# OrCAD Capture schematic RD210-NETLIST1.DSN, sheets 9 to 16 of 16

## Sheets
9 8: size Custom
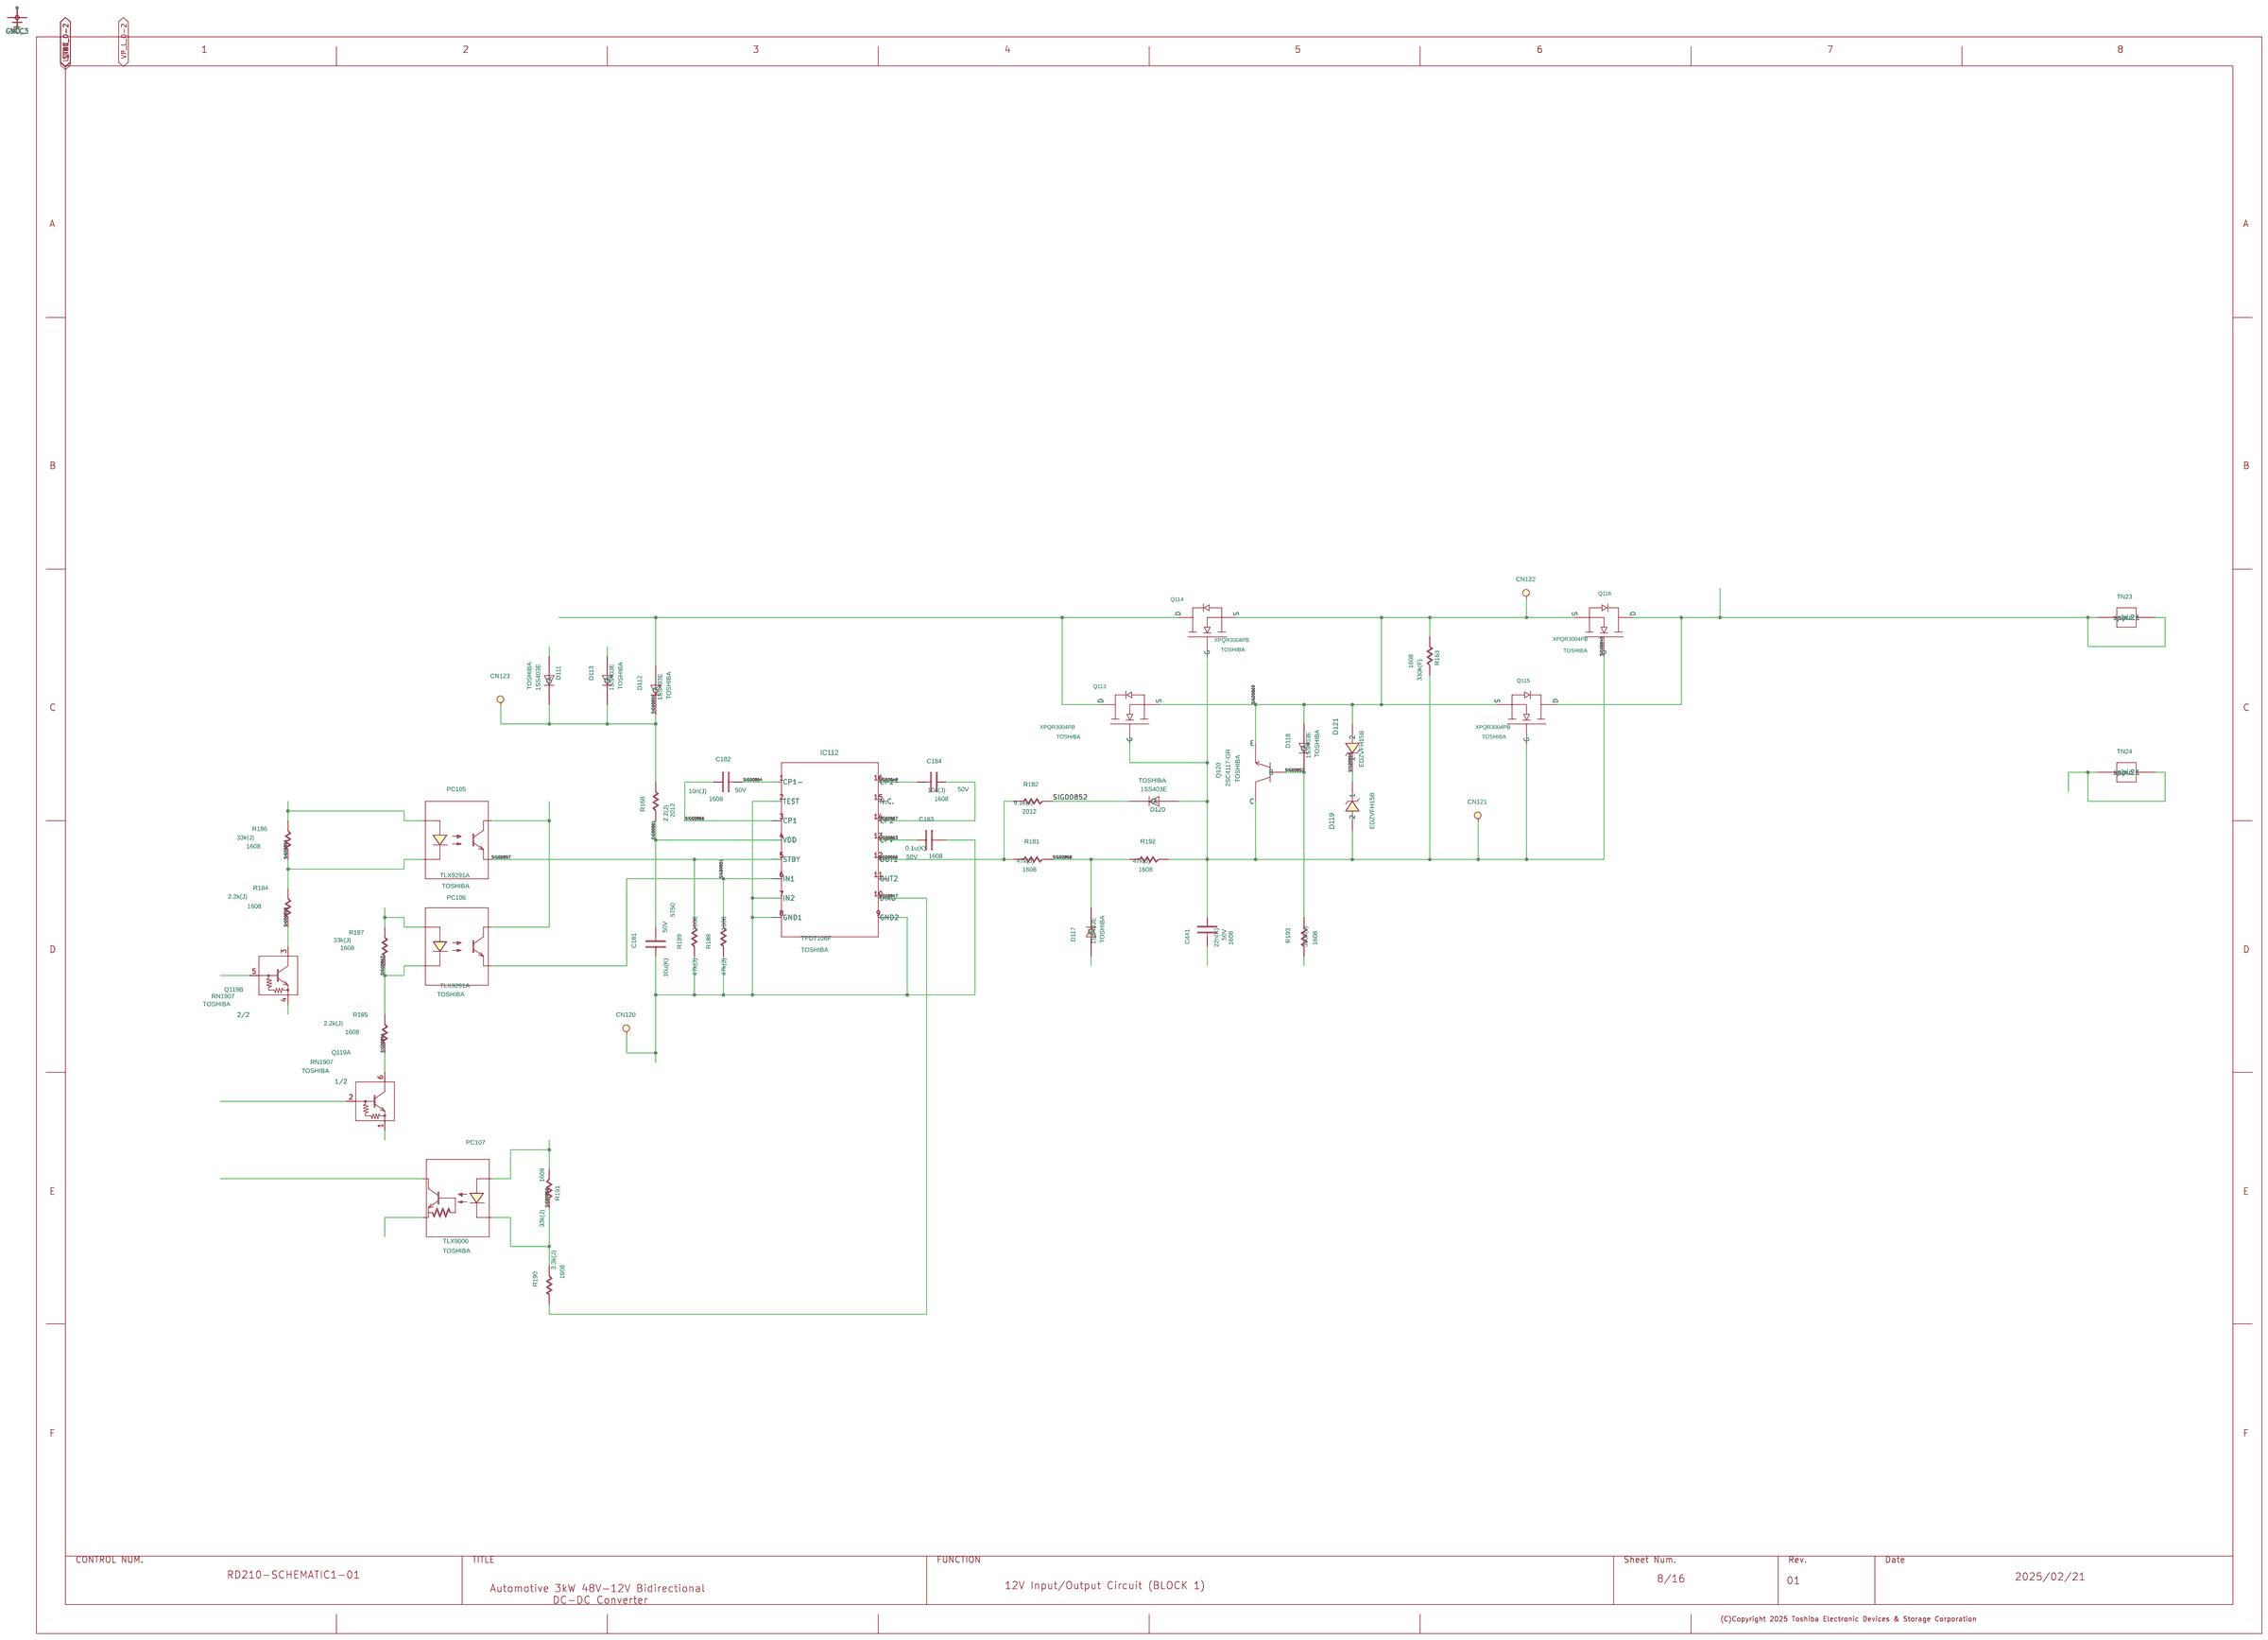
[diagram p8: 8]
10 7: size Custom
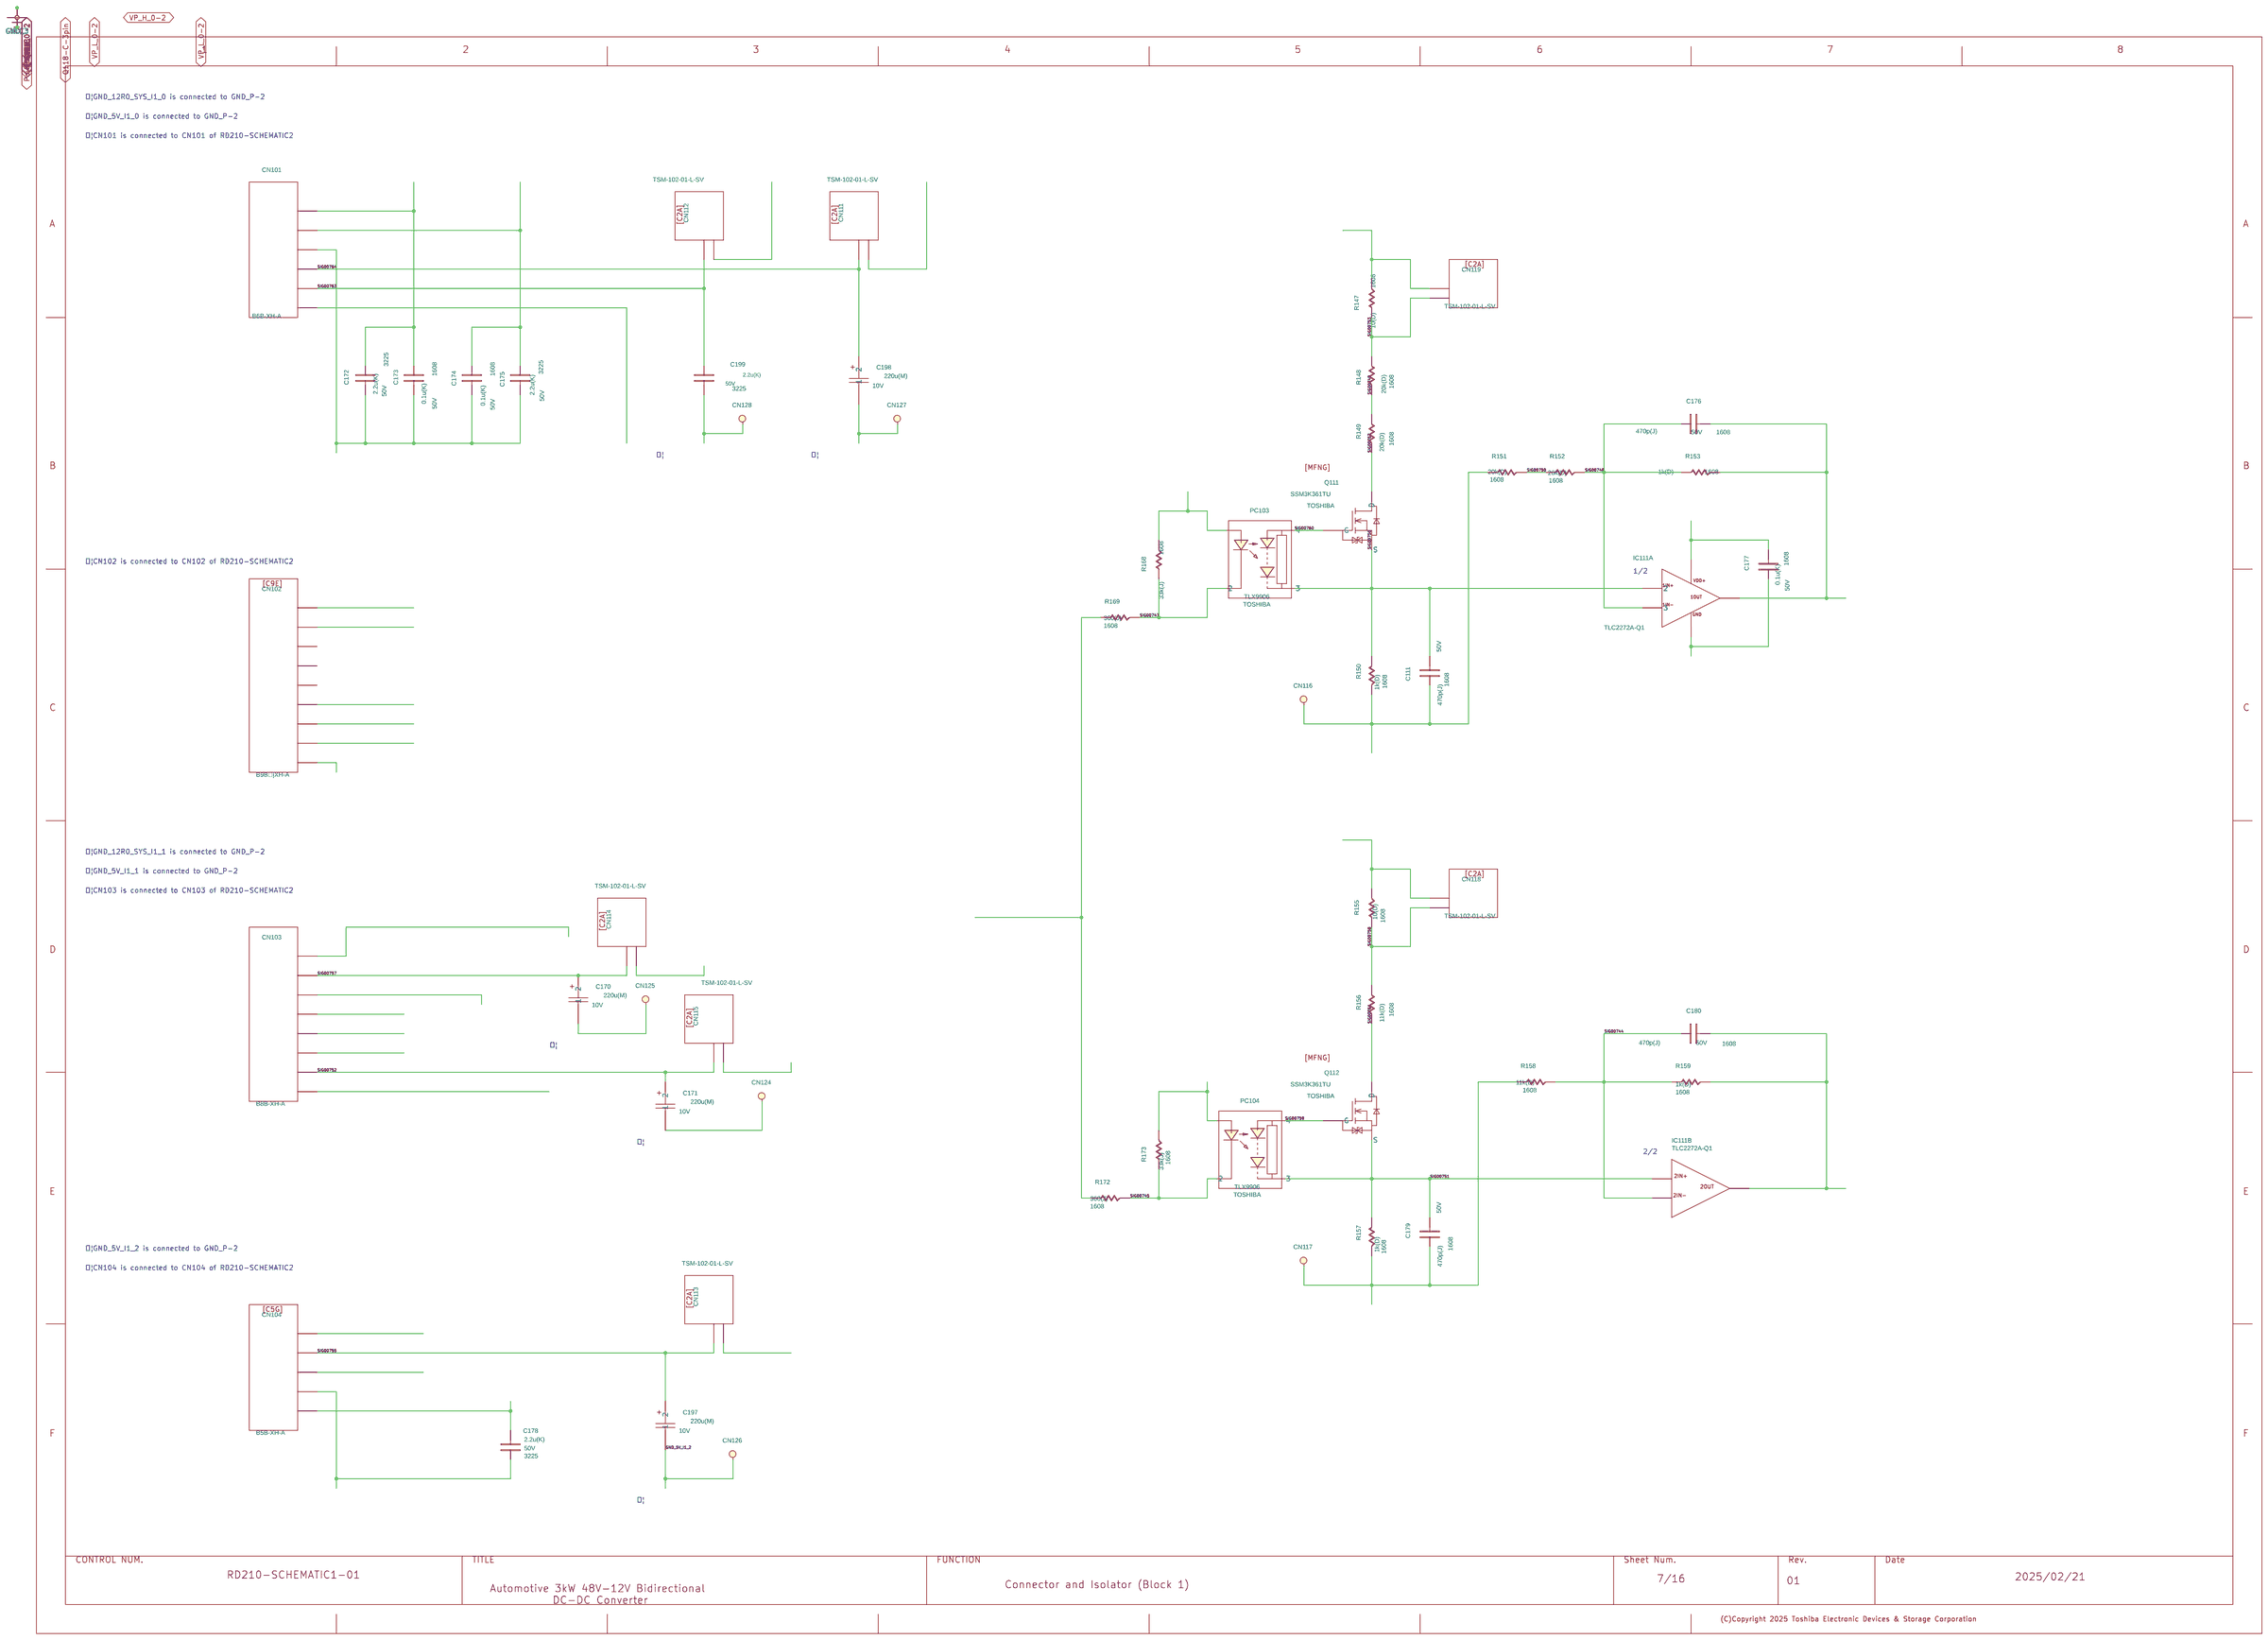
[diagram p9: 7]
11 6: size Custom
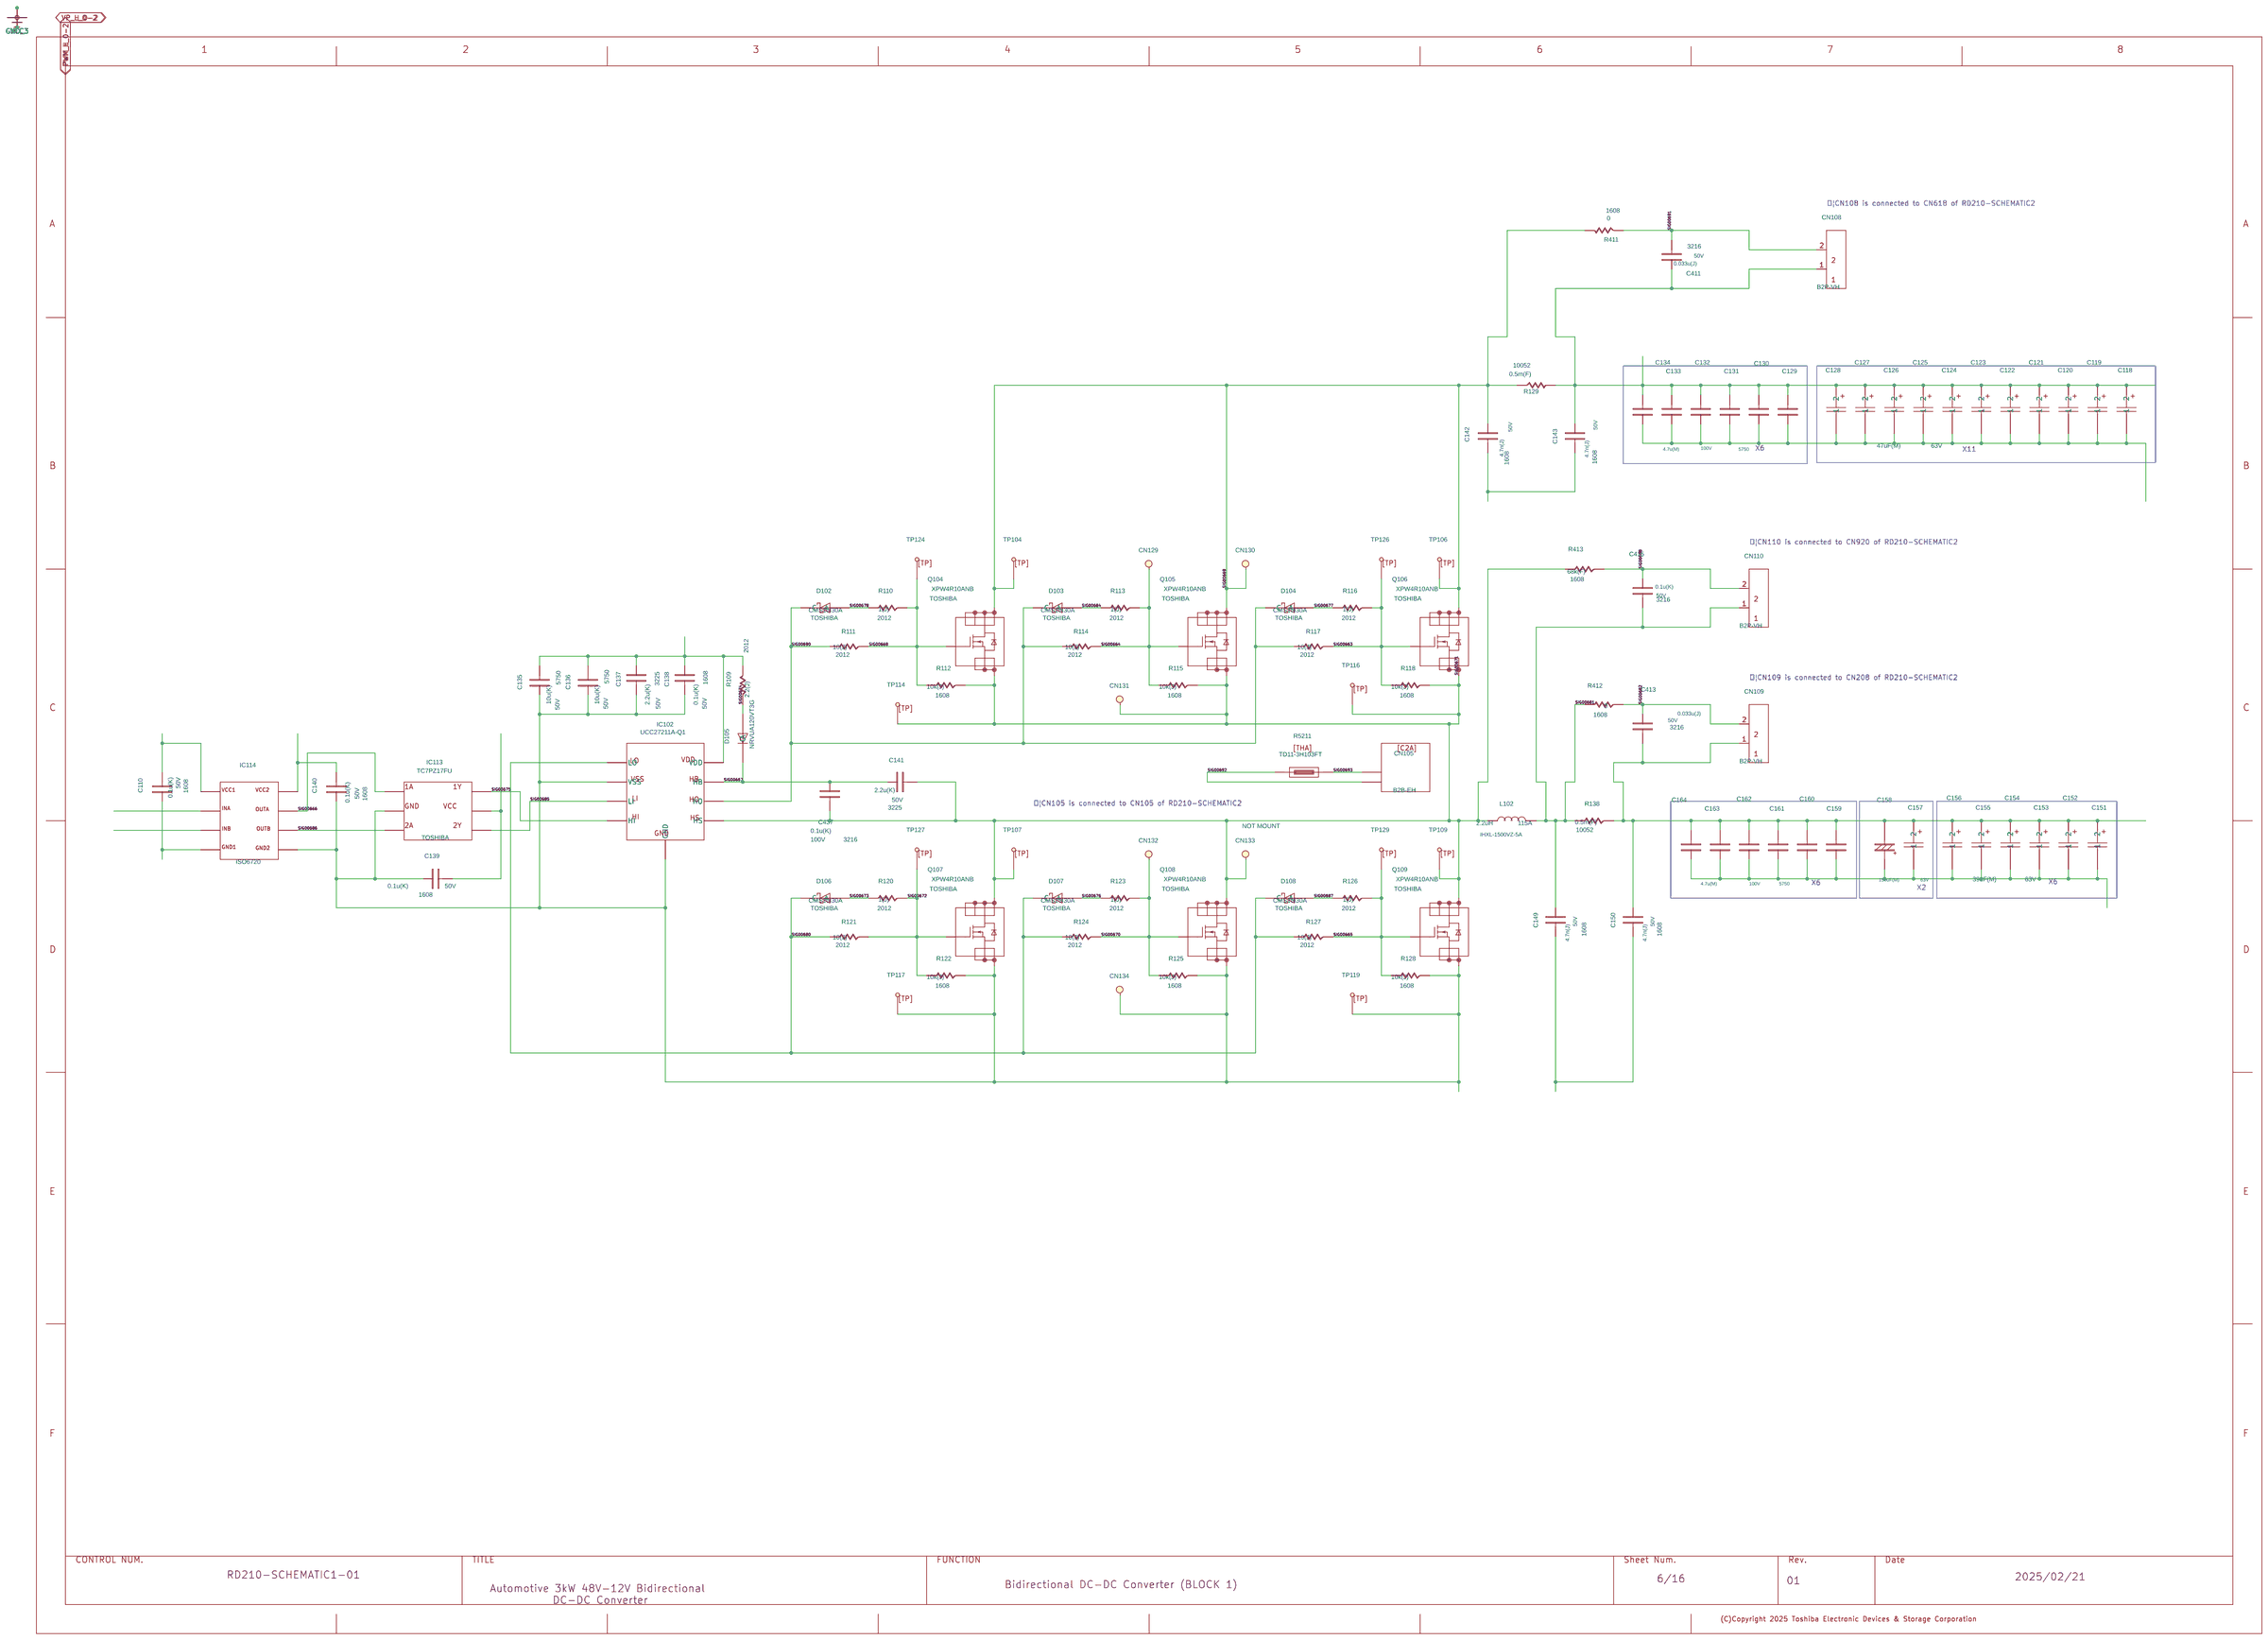
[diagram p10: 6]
12 5: size Custom
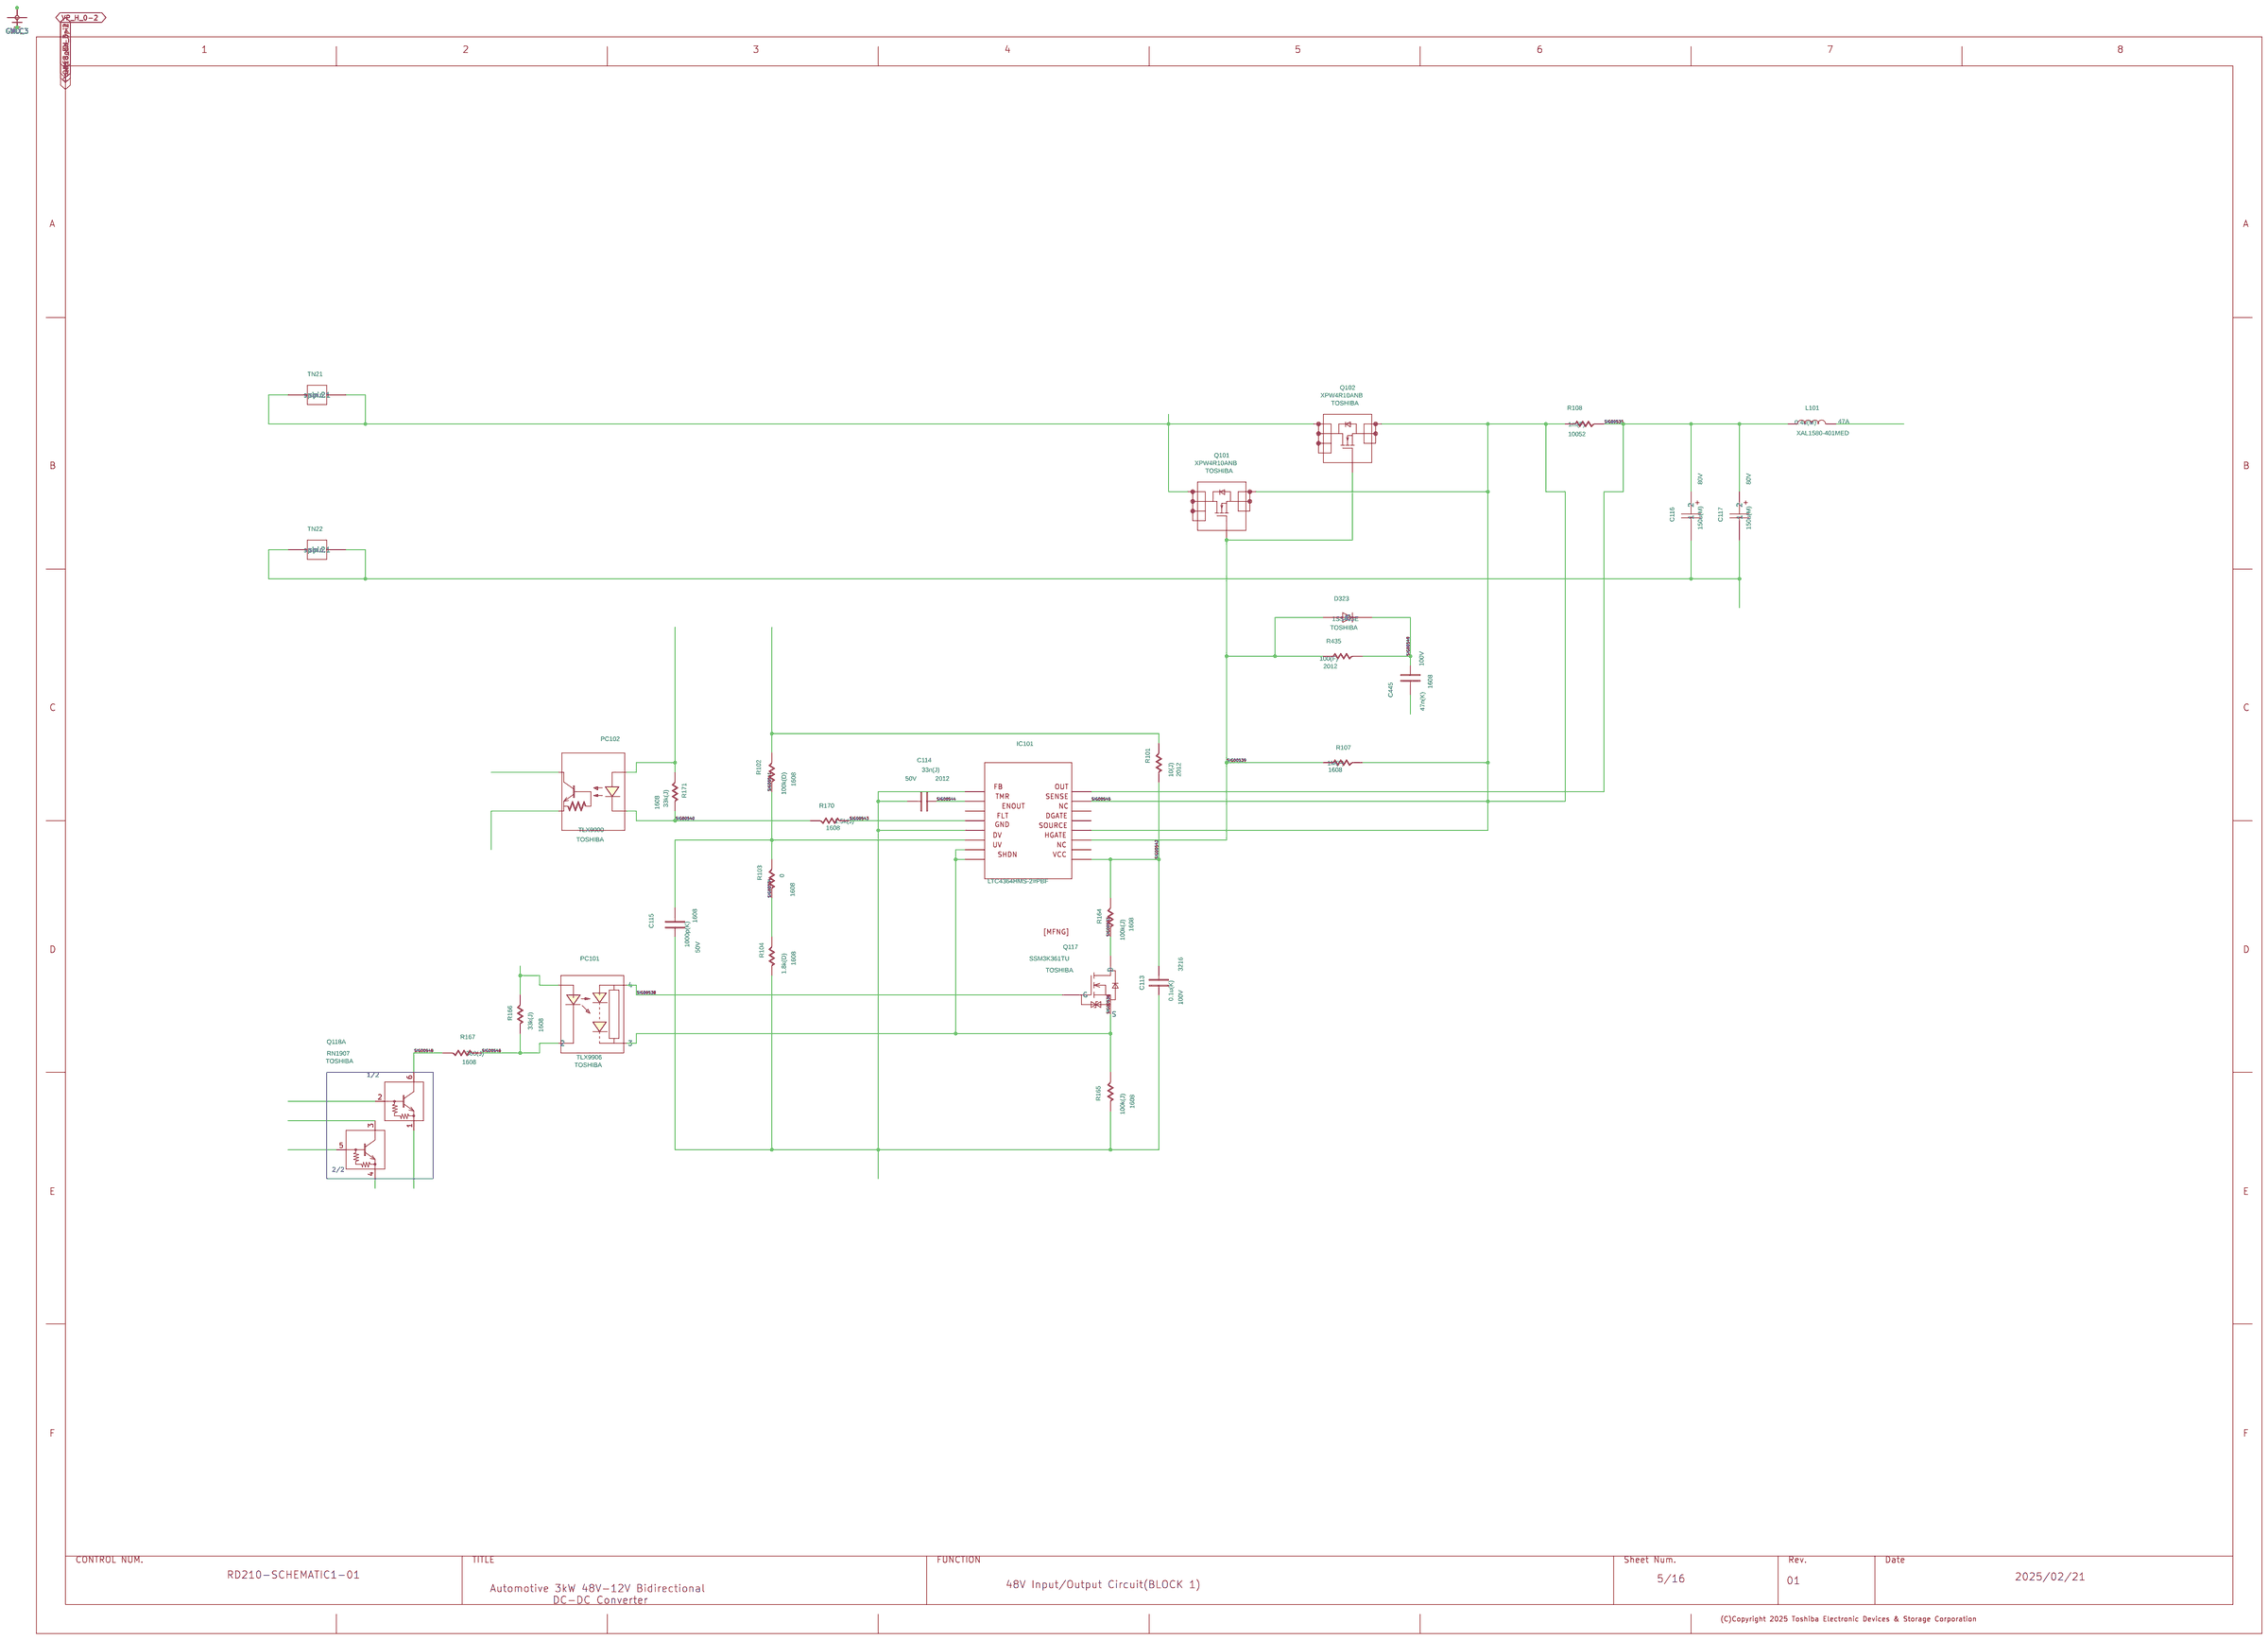
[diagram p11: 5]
13 4: size Custom
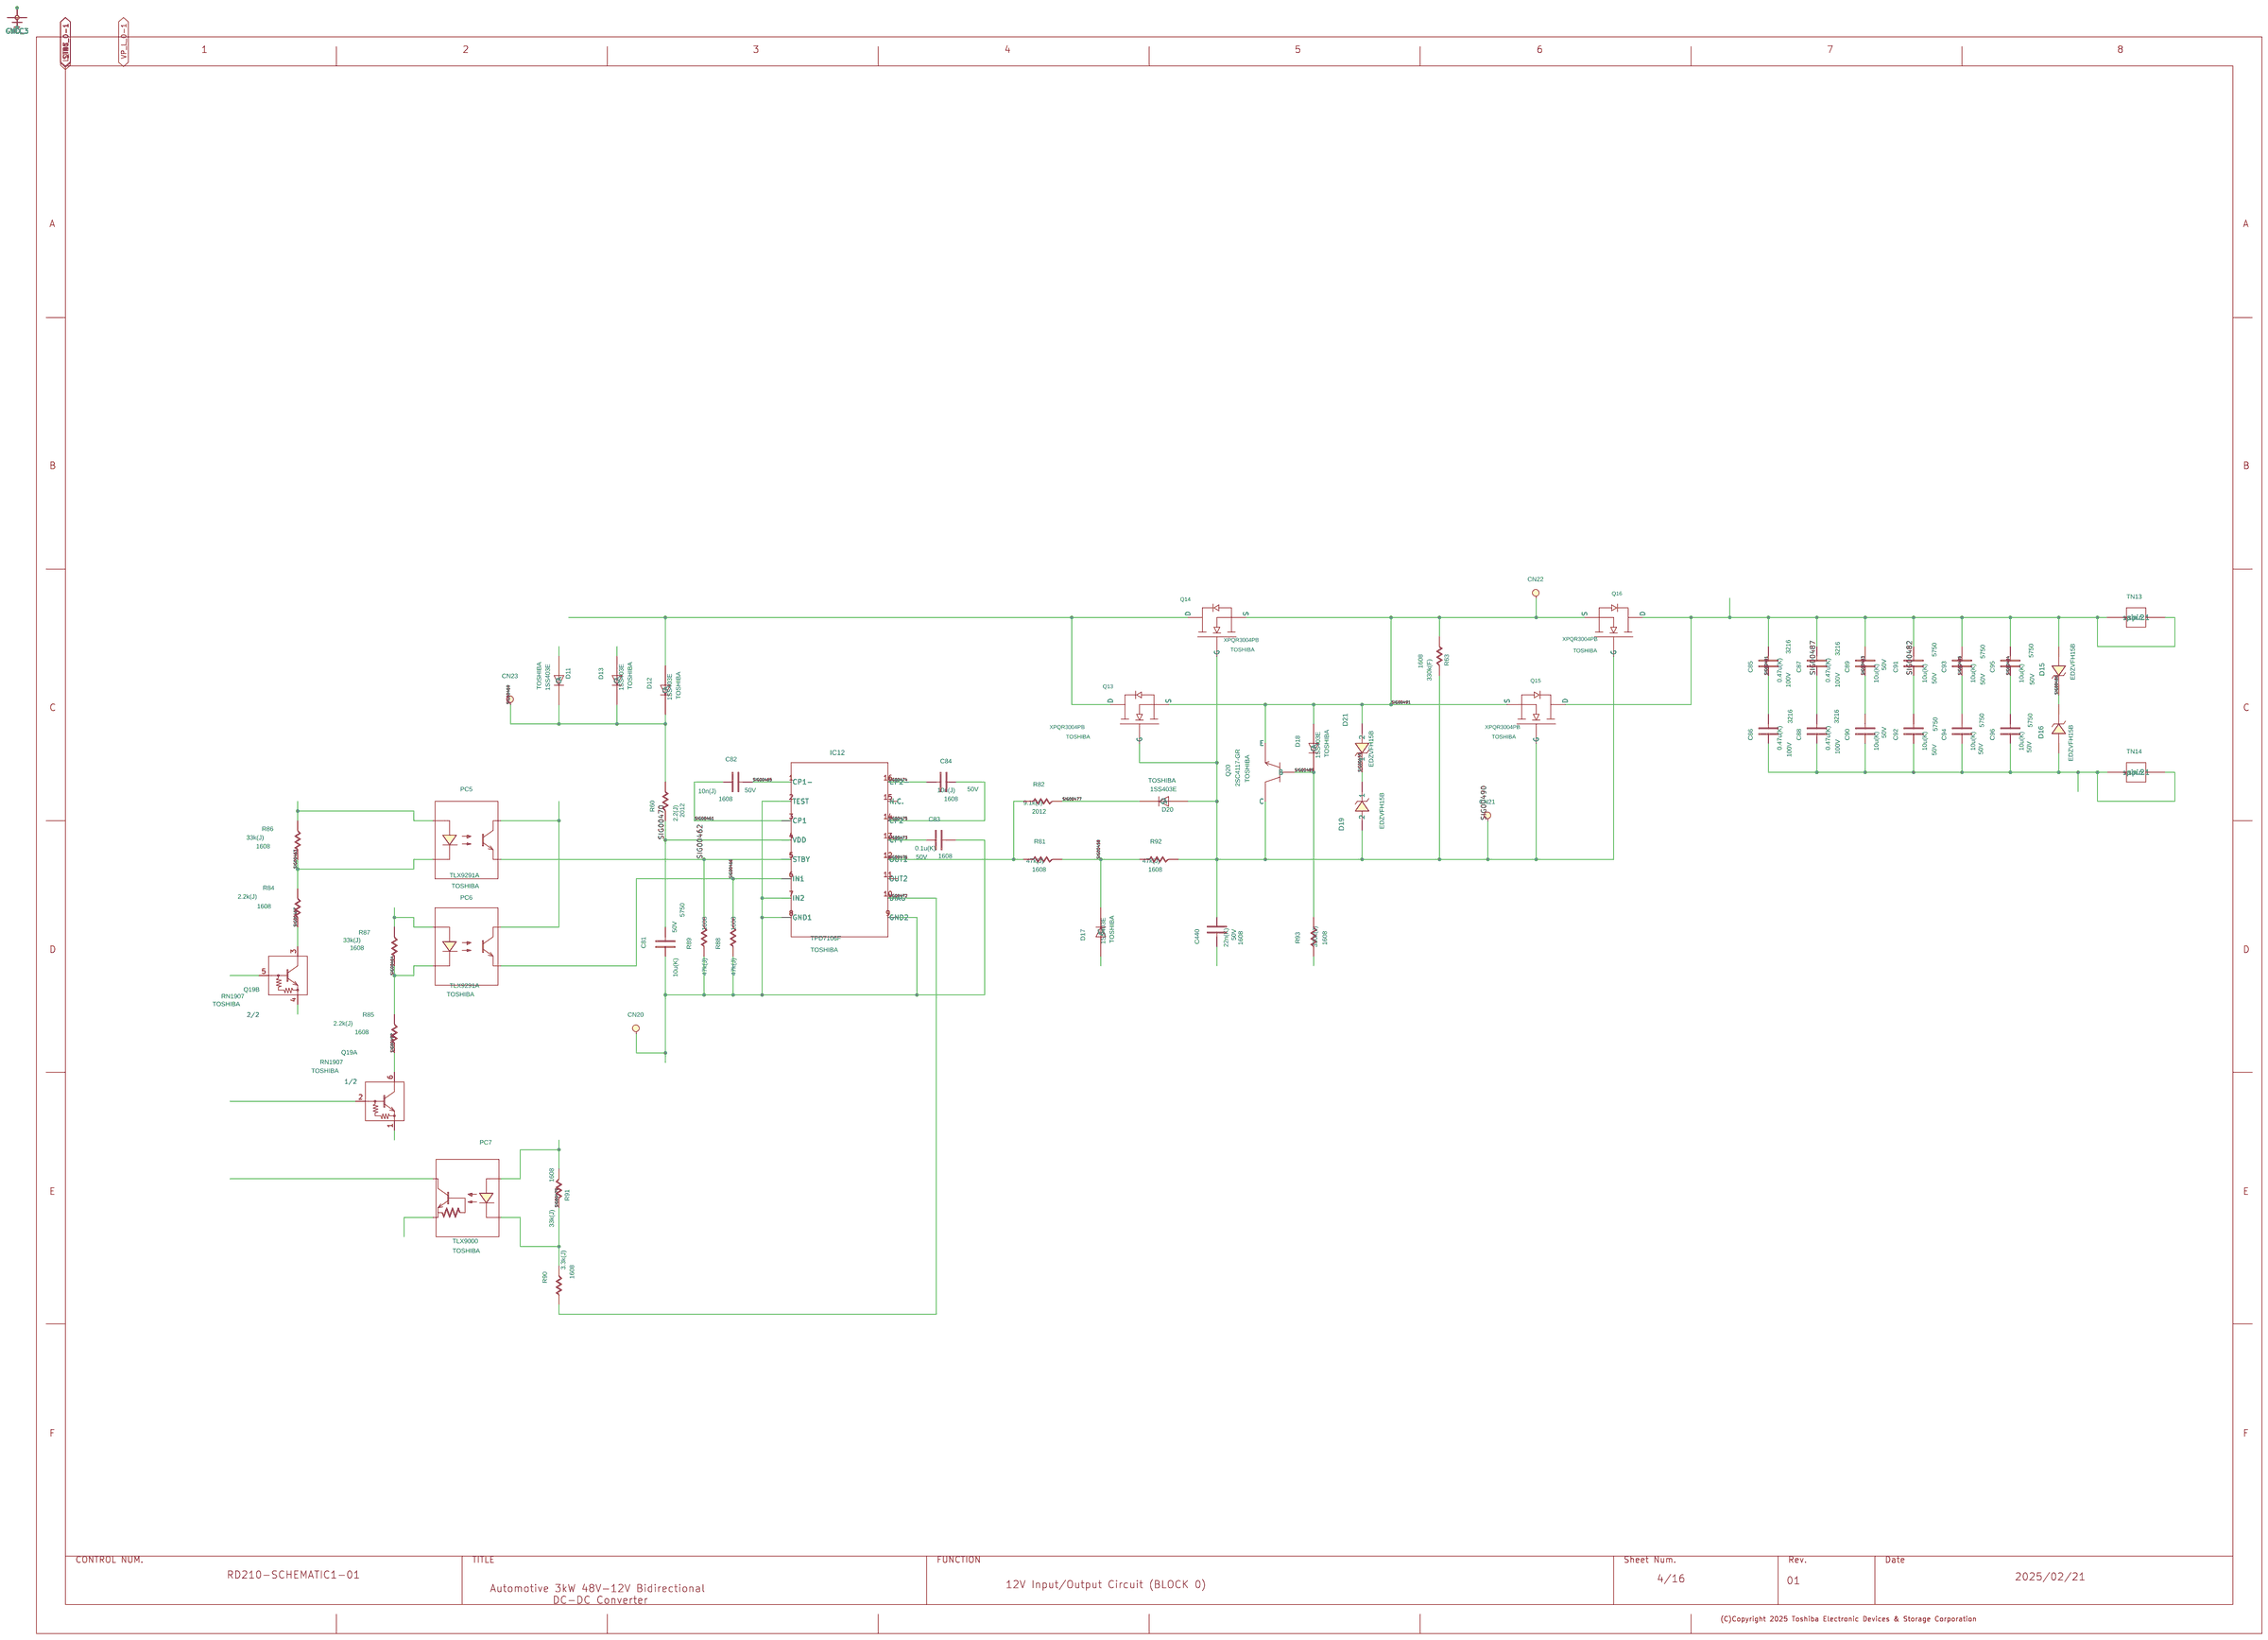
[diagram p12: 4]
14 3: size Custom
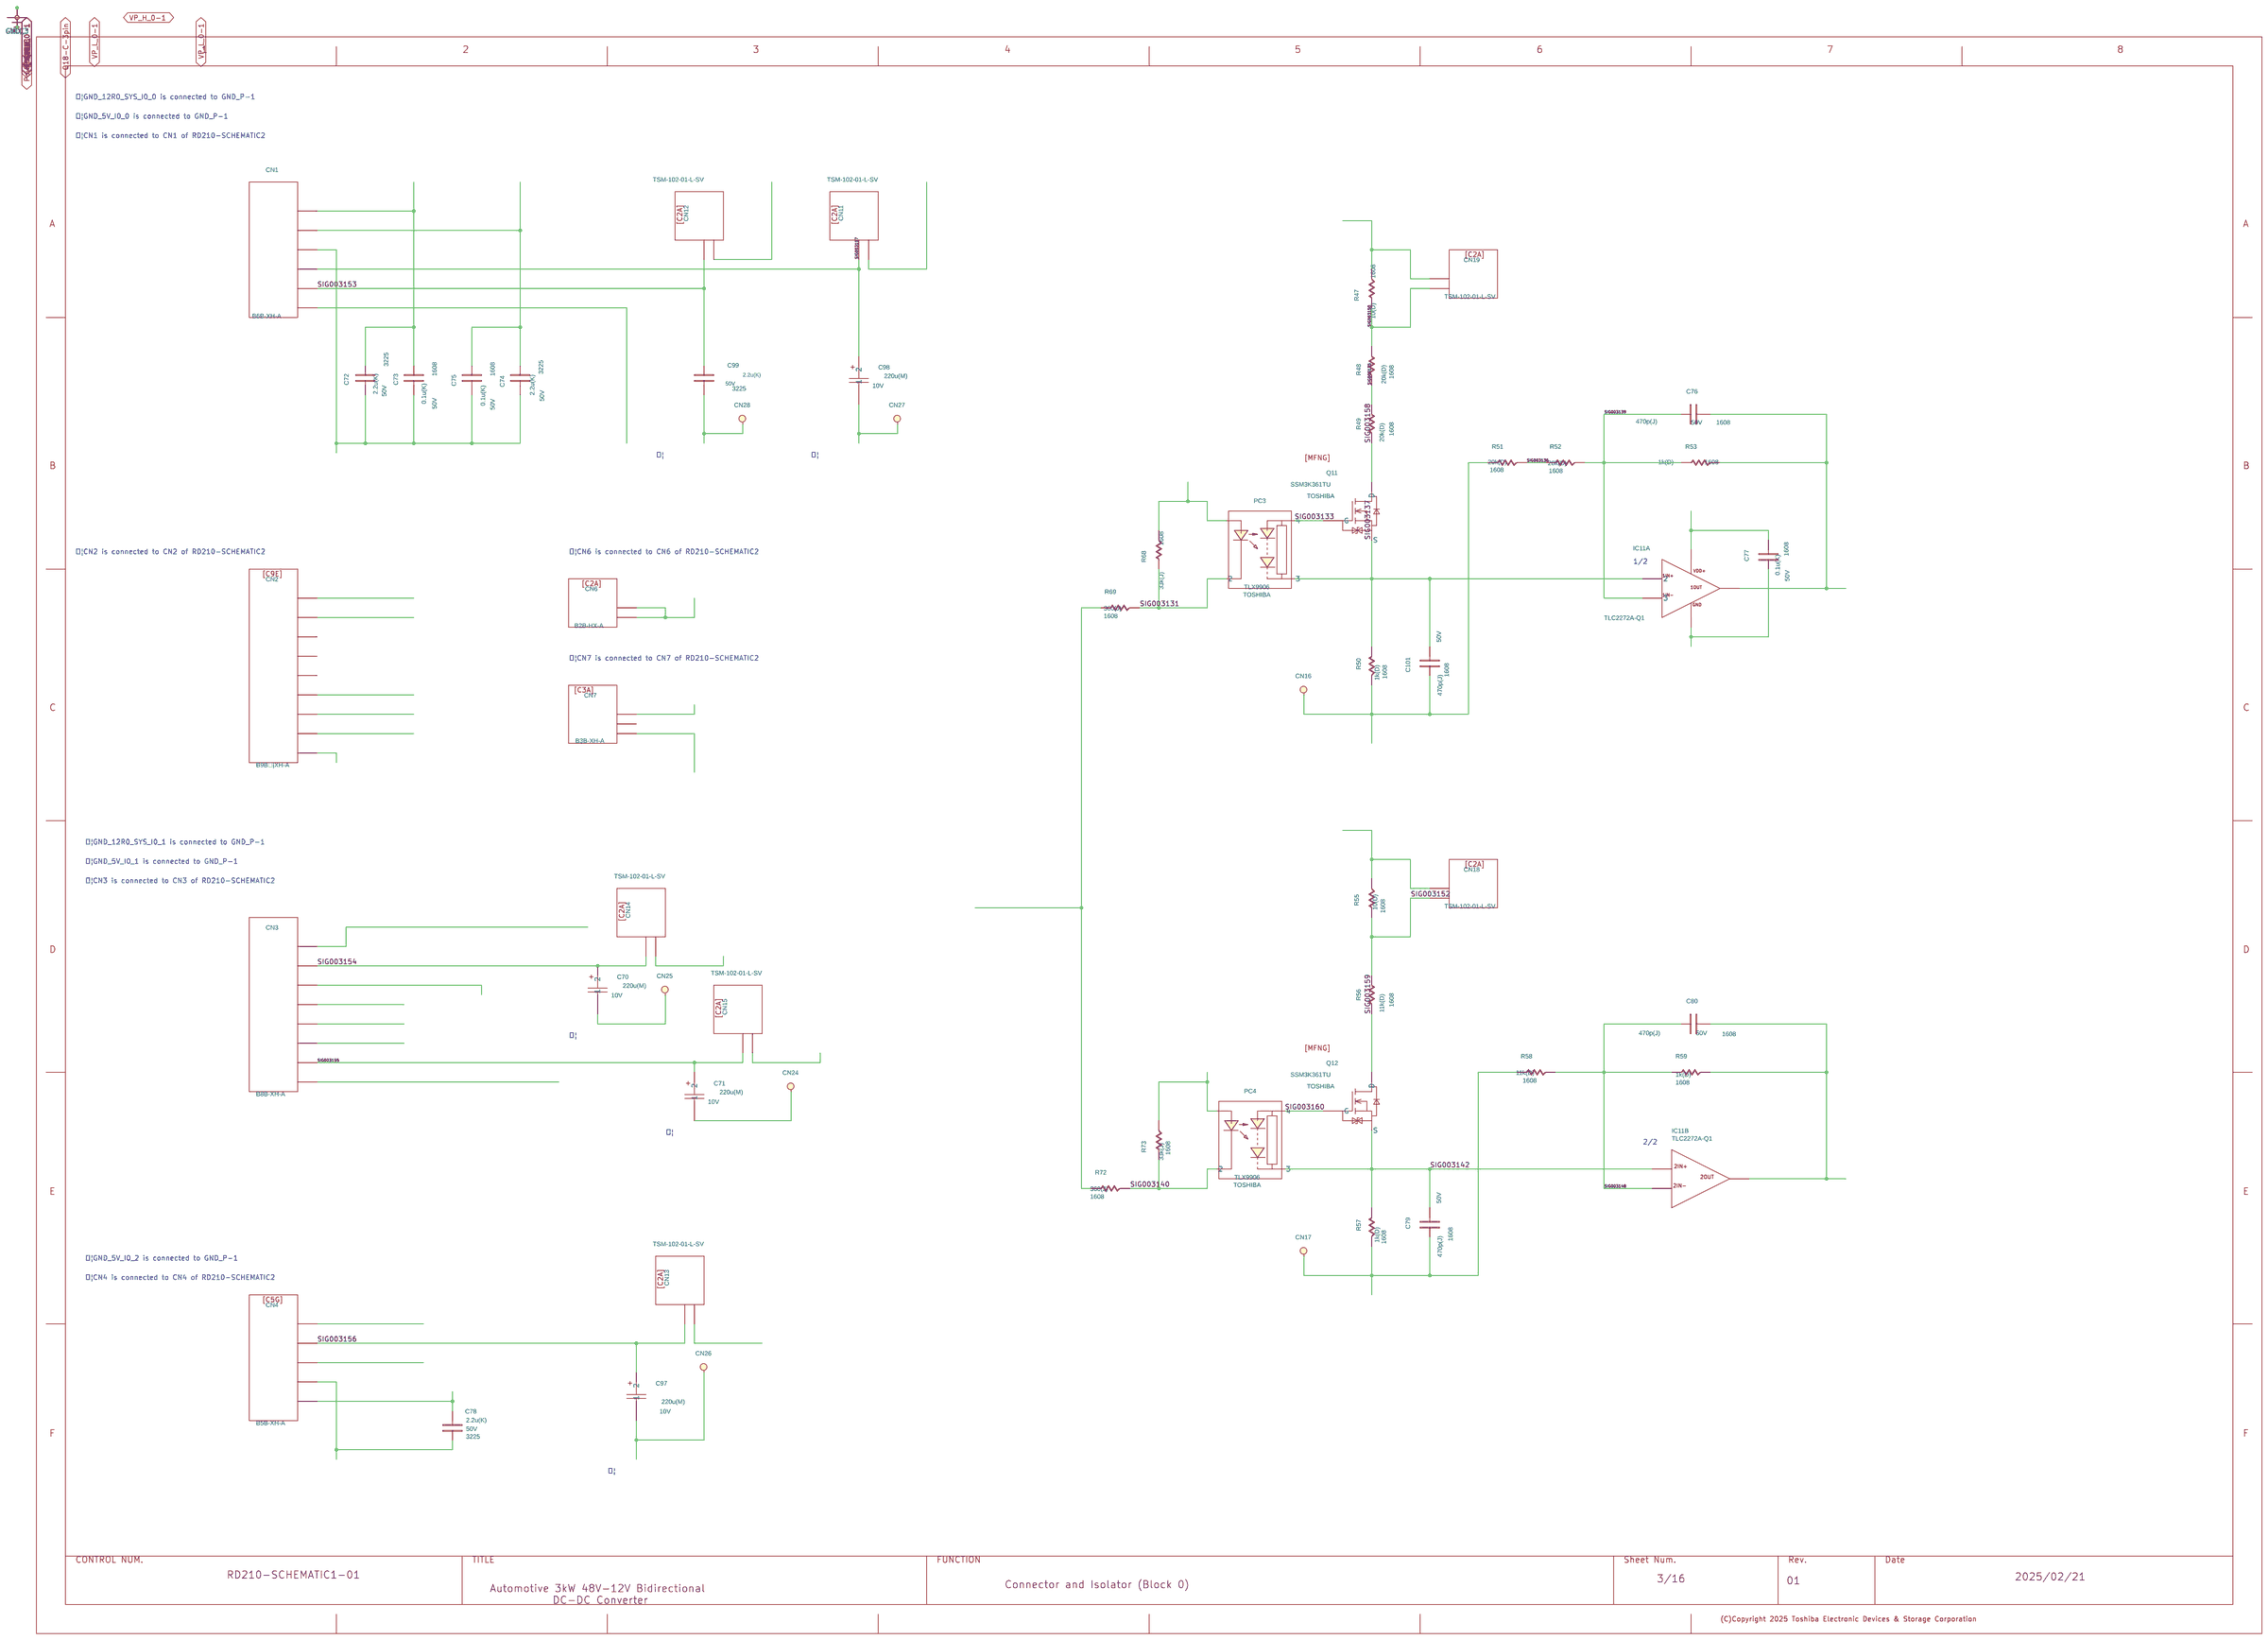
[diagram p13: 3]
15 2: size Custom
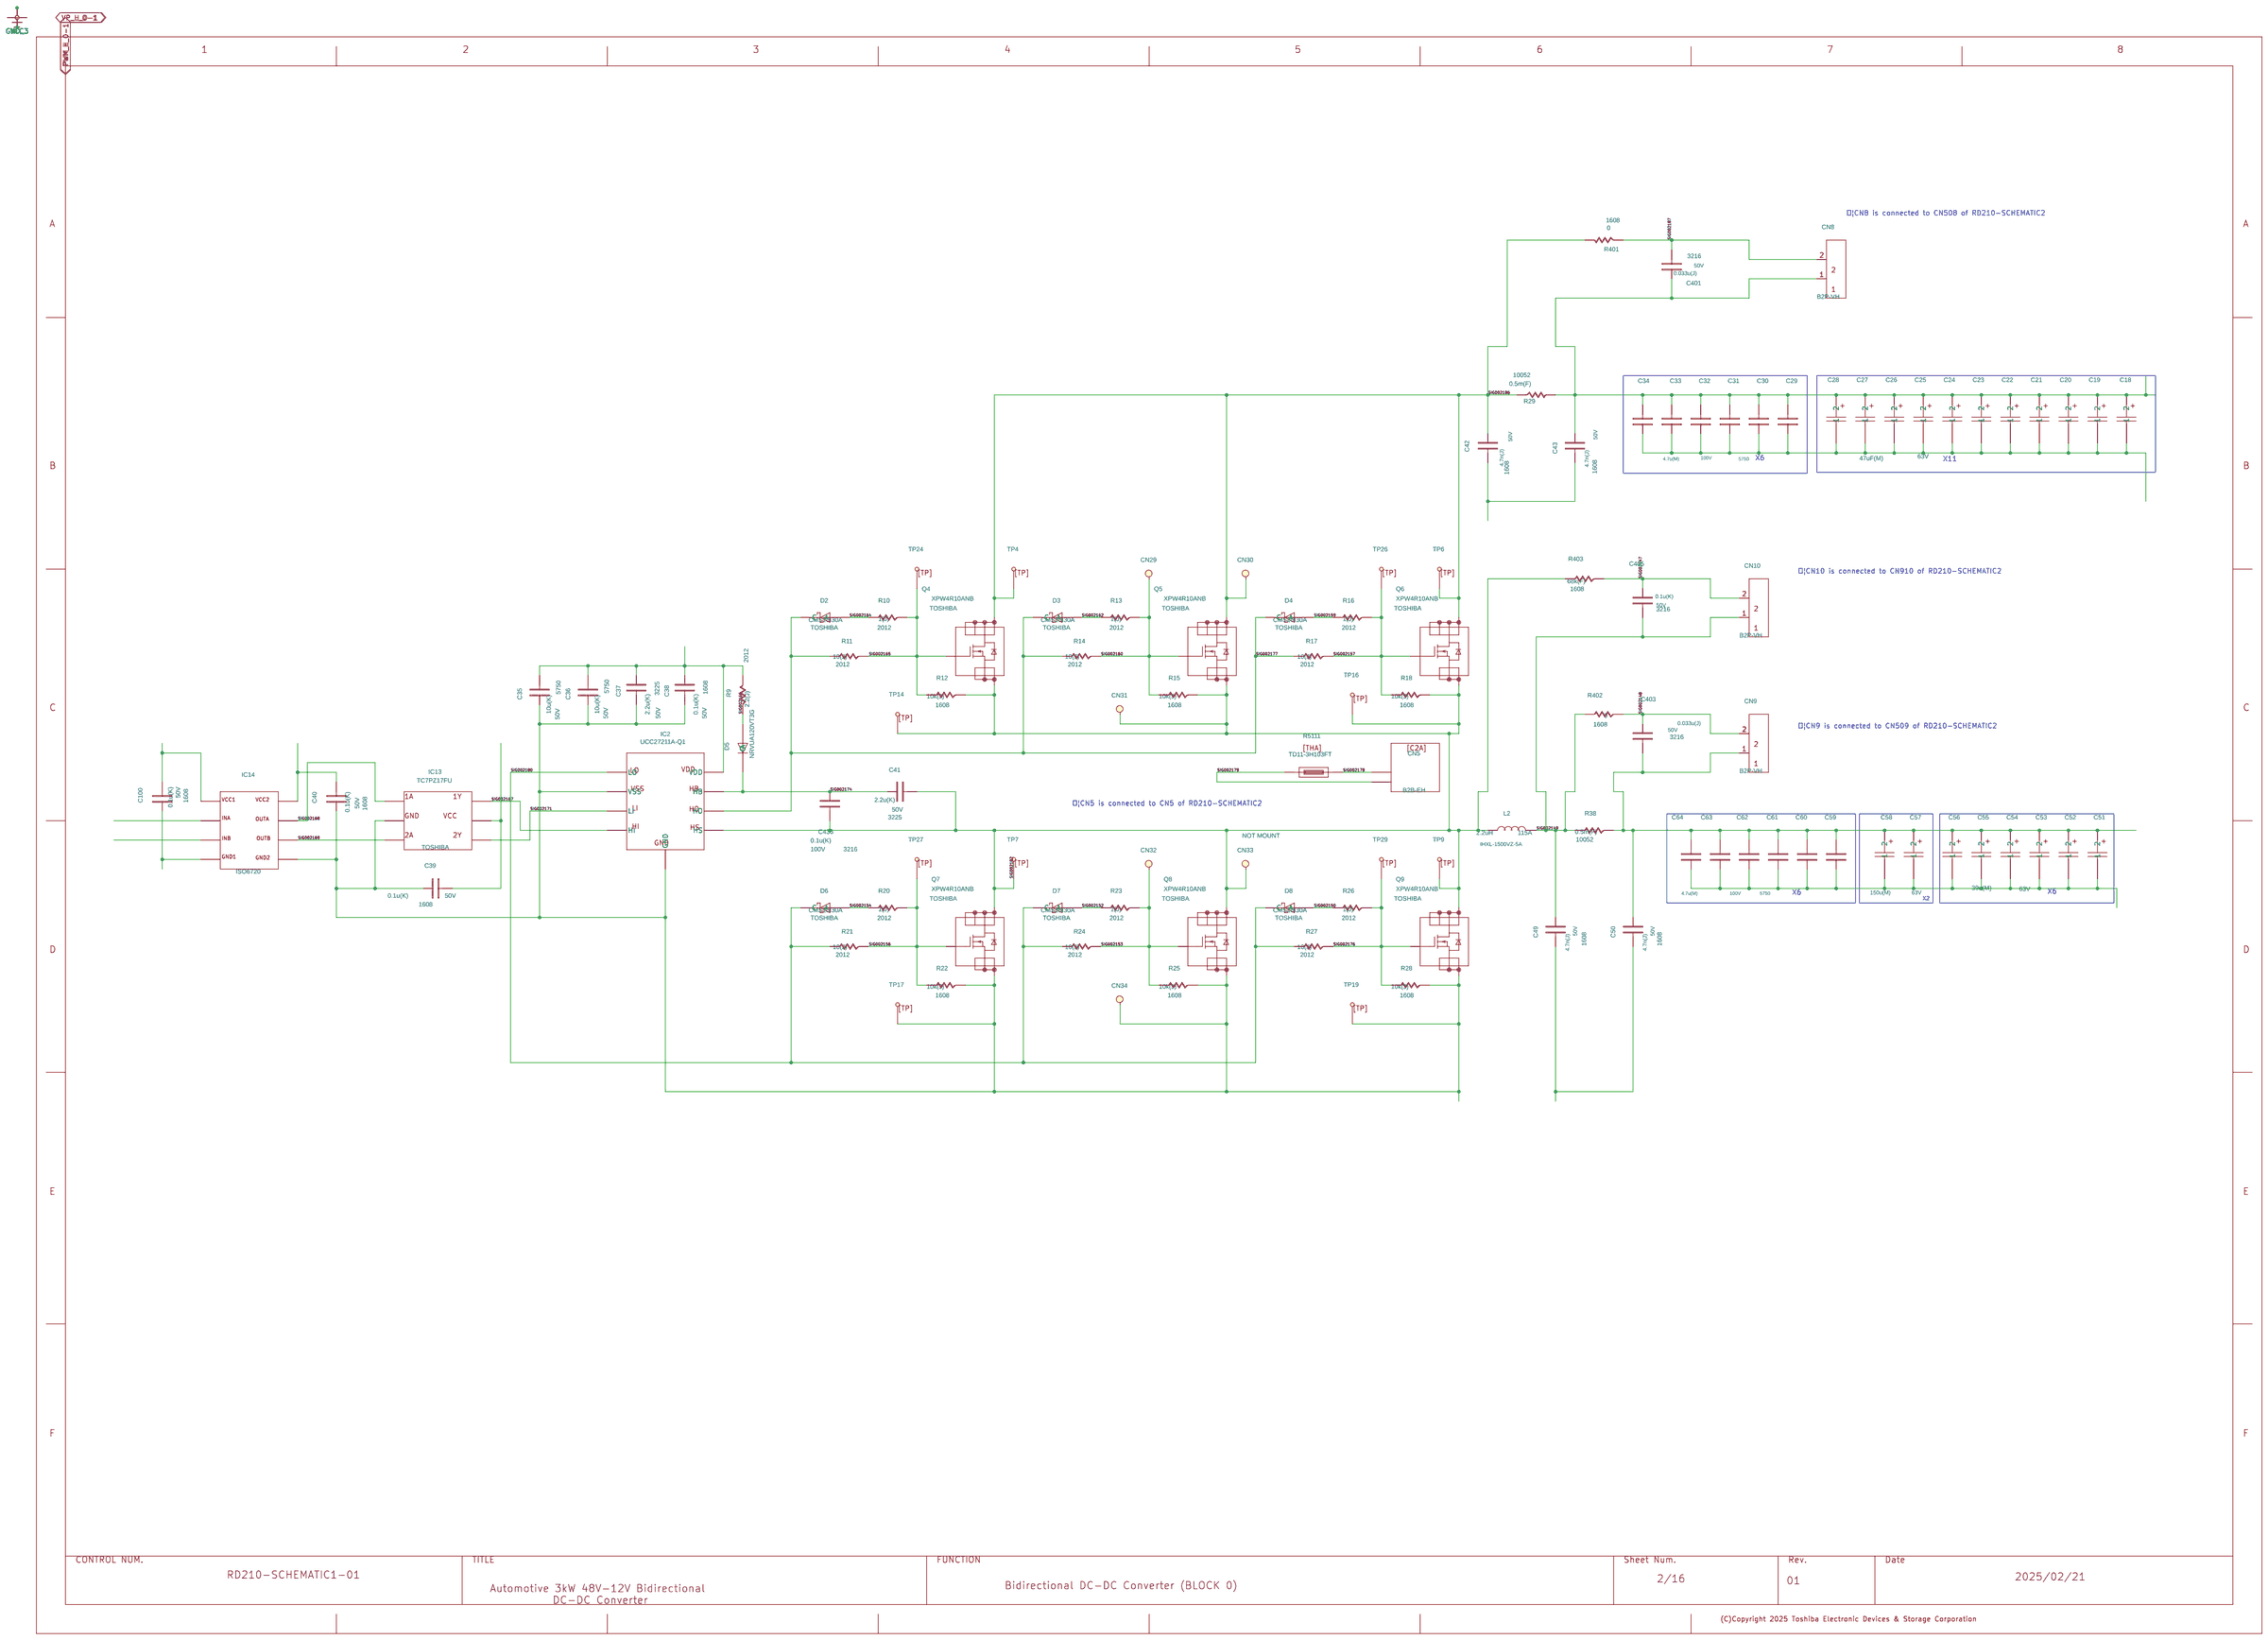
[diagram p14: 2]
16 1: size Custom
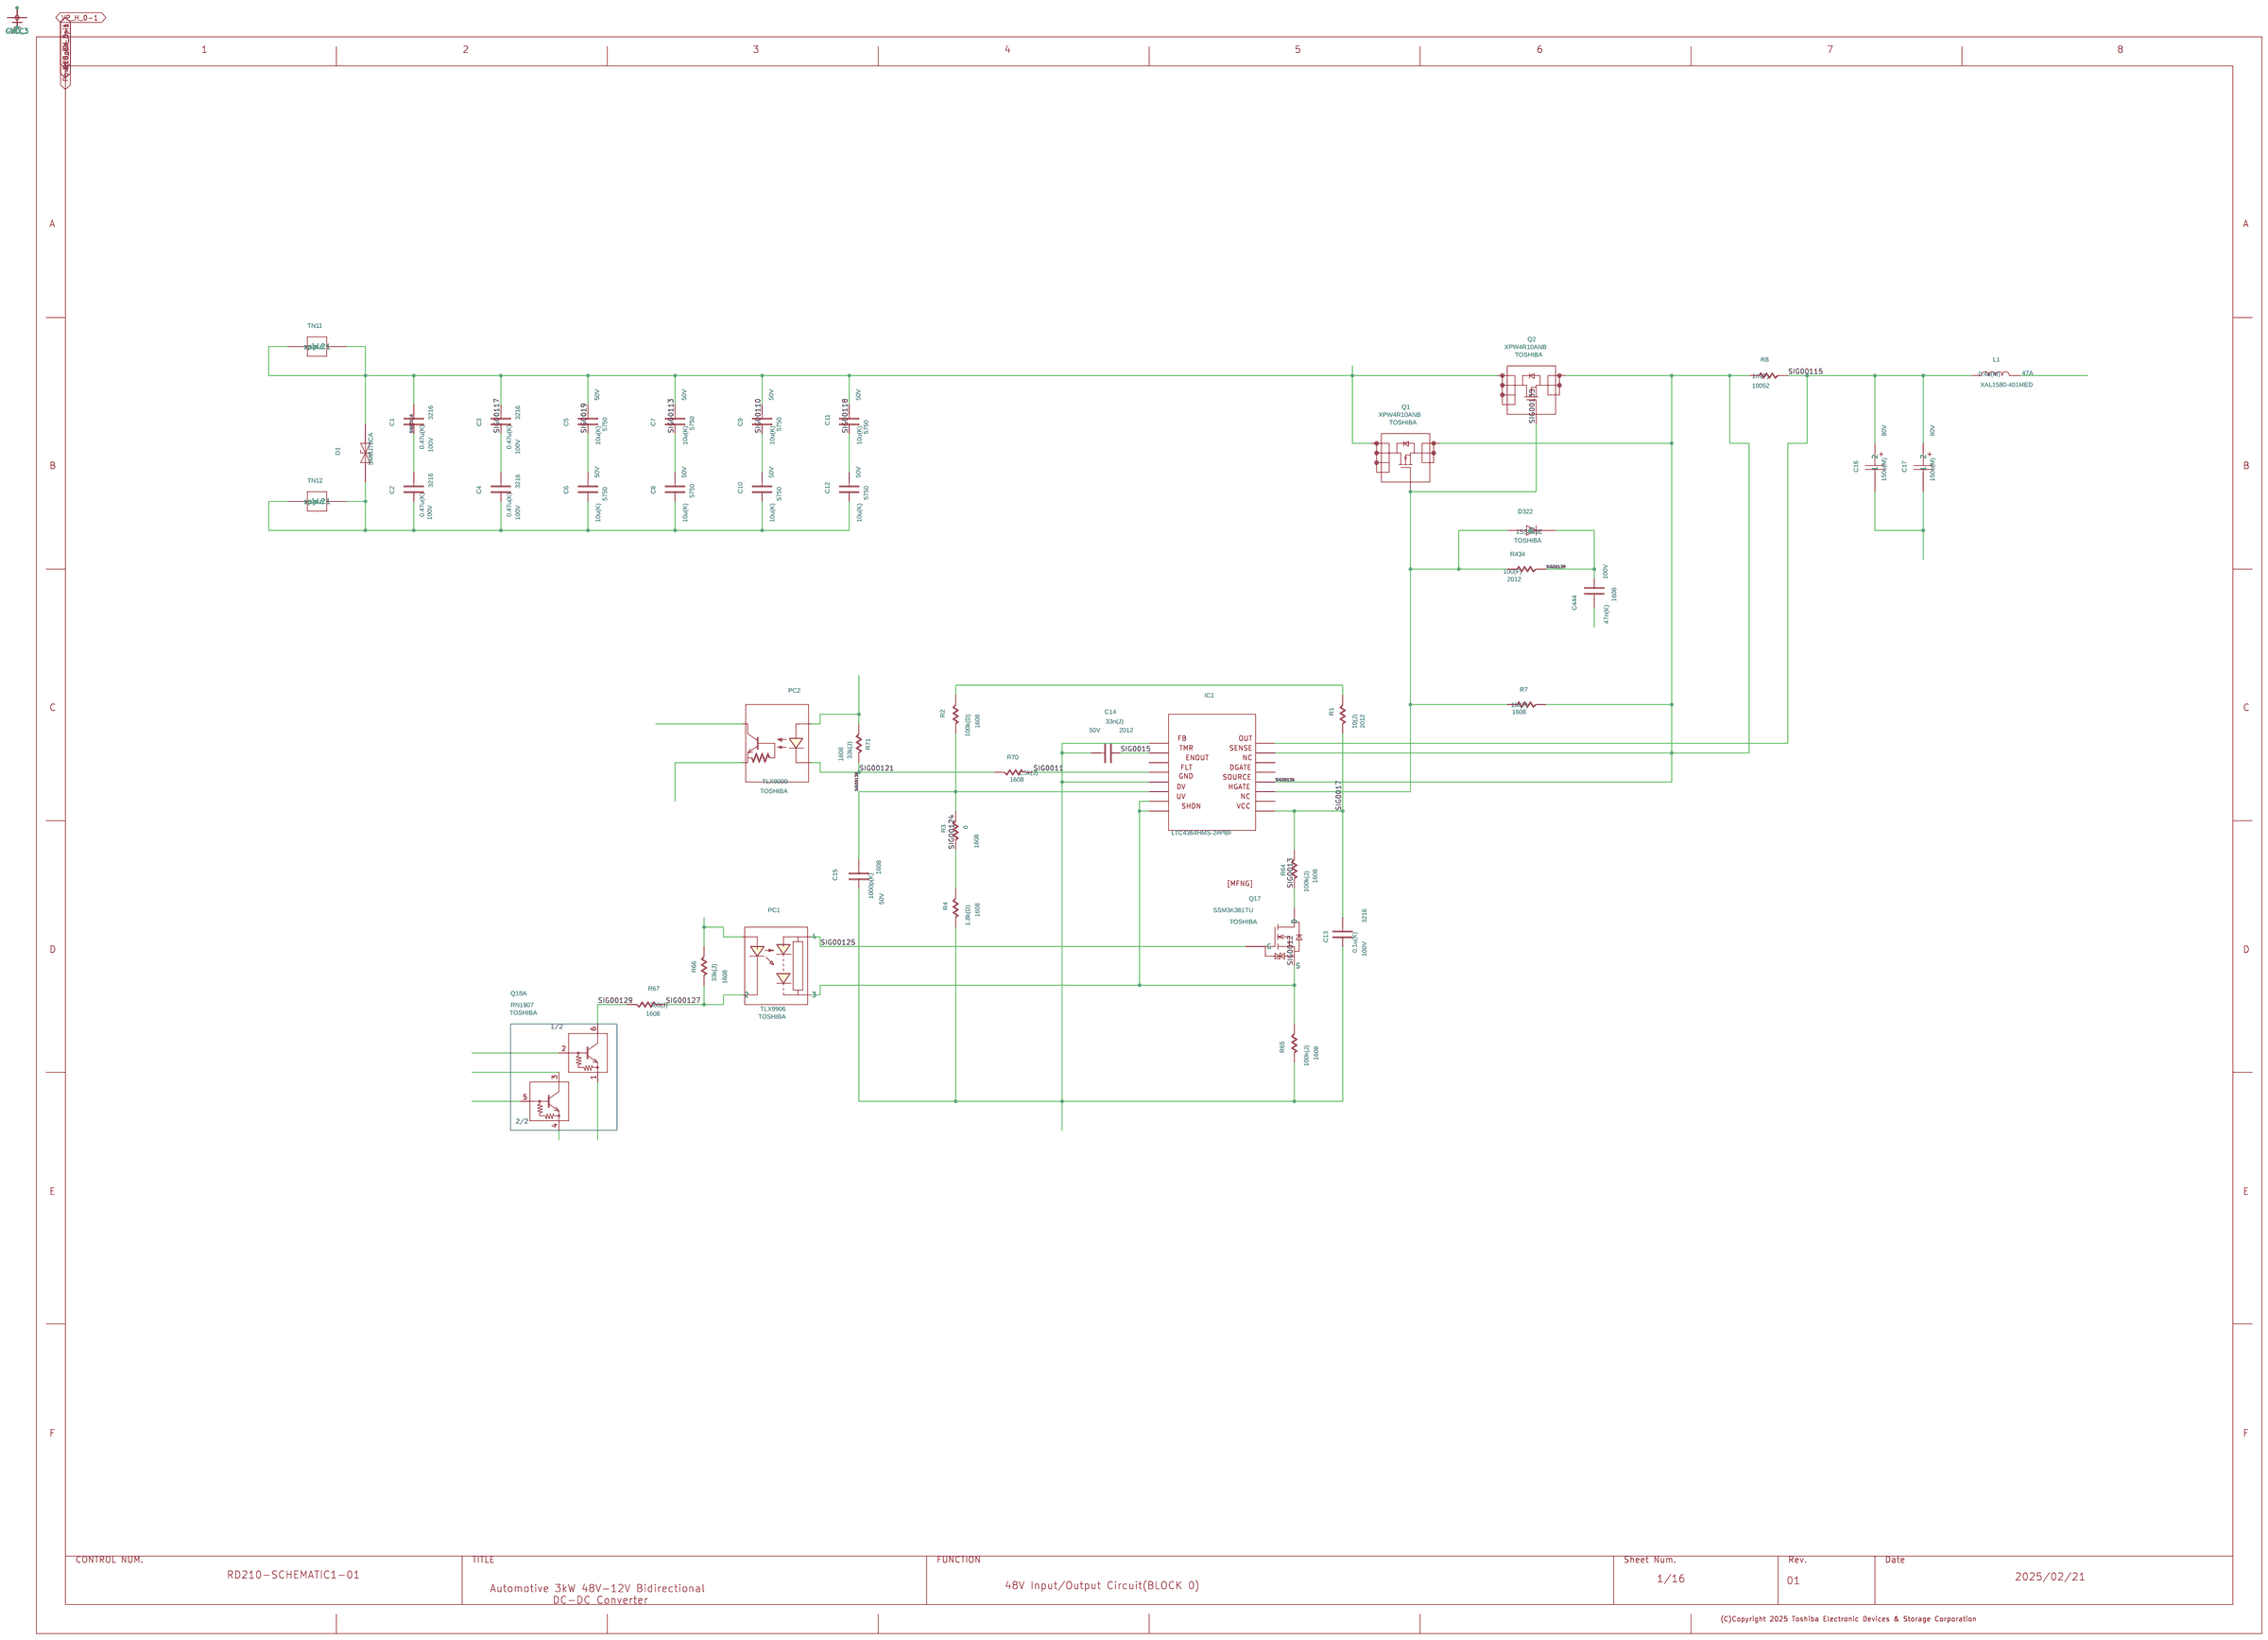
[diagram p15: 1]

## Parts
sheet 1
C1  C
C2  C
C3  C
C4  C
C5  C
C6  C
C7  C
C8  C
C9  C
C10  C
C11  C
C12  C
C13  C
C14  C
C15  C
C16  CP
C17  CP
C444  C
D1  DEL_12
D322  D
IC1  IS18
L1  L
PC1  TLX9906
PC2  TLX9000
Q1  MFNAJ_1
Q2  MFNAJ_1
Q17  MFNG
Q18  RN1907_Q1_1  (sections A,B)
R1  R
R2  R
R3  R
R4  R
R7  R
R8  R
R64  R
R65  R
R66  R
R67  R
R70  R
R71  R
R434  R
TN11  BOX_2
TN12  BOX_2
U?#15  WAKU_DEF_A3
sheet 2
C18  CP
C19  CP
C20  CP
C21  CP
C22  CP
C23  CP
C24  CP
C25  CP
C26  CP
C27  CP
C28  CP
C29  C
C30  C
C31  C
C32  C
C33  C
C34  C
C35  C
C36  C
C37  C
C38  C
C39  C
C40  C
C41  C
C42  C
C43  C
C49  C
C50  C
C51  CP
C52  CP
C53  CP
C54  CP
C55  CP
C56  CP
C57  CP
C58  CP
C59  C
C60  C
C61  C
C62  C
C63  C
C64  C
C100  C
C401  C
C403  C
C405  C
C436  C
CN5  C2A
CN8  B2P-VH
CN9  B2P-VH
CN10  B2P-VH
CN29  HM-TP08
CN30  HM-TP08
CN31  HM-TP08
CN32  HM-TP08
CN33  HM-TP08
CN34  HM-TP08
D2  SBD
D3  SBD
D4  SBD
D5  D
D6  SBD
D7  SBD
D8  SBD
IC2  UCC27211A_00
IC13  TC7PZ17FU
IC14  ISO6720_IC13
L2  L
Q4  MFNAJ_1
Q5  MFNAJ_1
Q6  MFNAJ_1
Q7  MFNAJ_1
Q8  MFNAJ_1
Q9  MFNAJ_1
R9  R
R10  R
R11  R
R12  R
R13  R
R14  R
R15  R
R16  R
R17  R
R18  R
R20  R
R21  R
R22  R
R23  R
R24  R
R25  R
R26  R
R27  R
R28  R
R29  R
R38  R
R401  R
R402  R
R403  R
R5111  THA
TP4  TP
TP6  TP
TP7  TP
TP9  TP
TP14  TP
TP16  TP
TP17  TP
TP19  TP
TP24  TP
TP26  TP
TP27  TP
TP29  TP
U?#14  WAKU_DEF_A3
sheet 3
C70  CP
C71  CP
C72  C
C73  C
C74  C
C75  C
C76  C
C77  C
C78  C
C79  C
C80  C
C97  CP
C98  CP
C99  C
C101  C
CN1  B6B-XH-A
CN2  C9E
CN3  B8B-XH-A
CN4  C5G
CN6  C2A
CN7  C3A
CN11  C2A
CN12  C2A
CN13  C2A
CN14  C2A
CN15  C2A
CN16  HM-TP08
CN17  HM-TP08
CN18  C2A
CN19  C2A
CN24  HM-TP08
CN25  HM-TP08
CN26  HM-TP08
CN27  HM-TP08
CN28  HM-TP08
IC11  NA  (sections A,B)
PC3  TLX9906
PC4  TLX9906
Q11  MFNG
Q12  MFNG
R47  R
R48  R
R49  R
R50  R
R51  R
R52  R
R53  R
R55  R
R56  R
R57  R
R58  R
R59  R
R68  R
R69  R
R72  R
R73  R
U?#13  WAKU_DEF_A3
sheet 4
C81  C
C82  C
C83  C
C84  C
C85  C
C86  C
C87  C
C88  C
C89  C
C90  C
C91  C
C92  C
C93  C
C94  C
C95  C
C96  C
C440  C
CN20  HM-TP08
CN21  HM-TP08
CN22  HM-TP08
CN23  HM-TP08
D11  D
D12  D
D13  D
D15  -
D16  -
D17  D
D18  D
D19  -
D20  D
D21  -
IC12  TLP5231
PC5  TLX9291A
PC6  TLX9291A
PC7  TLX9000
Q13  SSM3K318R
Q14  SSM3K318R
Q15  SSM3K318R
Q16  SSM3K318R
Q19  RN1907_Q1_1  (sections A,B)
Q20  TRN
R60  R
R63  R
R81  R
R82  R
R84  R
R85  R
R86  R
R87  R
R88  R
R89  R
R90  R
R91  R
R92  R
R93  R
TN13  BOX_2
TN14  BOX_2
U?#12  WAKU_DEF_A3
sheet 5
C113  C
C114  C
C115  C
C116  CP
C117  CP
C445  C
D323  D
IC101  IS18
L101  L
PC101  TLX9906
PC102  TLX9000
Q101  MFNAJ_1
Q102  MFNAJ_1
Q117  MFNG
Q118  RN1907_Q1_1  (sections A,B)
R101  R
R102  R
R103  R
R104  R
R107  R
R108  R
R164  R
R165  R
R166  R
R167  R
R170  R
R171  R
R435  R
TN21  BOX_2
TN22  BOX_2
U?#11  WAKU_DEF_A3
sheet 6
C110  C
C118  CP
C119  CP
C120  CP
C121  CP
C122  CP
C123  CP
C124  CP
C125  CP
C126  CP
C127  CP
C128  CP
C129  C
C130  C
C131  C
C132  C
C133  C
C134  C
C135  C
C136  C
C137  C
C138  C
C139  C
C140  C
C141  C
C142  C
C143  C
C149  C
C150  C
C151  CP
C152  CP
C153  CP
C154  CP
C155  CP
C156  CP
C157  CP
C158  C_00
C159  C
C160  C
C161  C
C162  C
C163  C
C164  C
C411  C
C413  C
C415  C
C437  C
CN105  C2A
CN108  B2P-VH
CN109  B2P-VH
CN110  B2P-VH
CN129  HM-TP08
CN130  HM-TP08
CN131  HM-TP08
CN132  HM-TP08
CN133  HM-TP08
CN134  HM-TP08
D102  SBD
D103  SBD
D104  SBD
D105  D
D106  SBD
D107  SBD
D108  SBD
IC102  UCC27211A_00
IC113  TC7PZ17FU
IC114  ISO6720_IC13
L102  L
Q104  MFNAJ_1
Q105  MFNAJ_1
Q106  MFNAJ_1
Q107  MFNAJ_1
Q108  MFNAJ_1
Q109  MFNAJ_1
R109  R
R110  R
R111  R
R112  R
R113  R
R114  R
R115  R
R116  R
R117  R
R118  R
R120  R
R121  R
R122  R
R123  R
R124  R
R125  R
R126  R
R127  R
R128  R
R129  R
R138  R
R411  R
R412  R
R413  R
R5211  THA
TP104  TP
TP106  TP
TP107  TP
TP109  TP
TP114  TP
TP116  TP
TP117  TP
TP119  TP
TP124  TP
TP126  TP
TP127  TP
TP129  TP
U?#10  WAKU_DEF_A3
sheet 7
C111  C
C170  CP
C171  CP
C172  C
C173  C
C174  C
C175  C
C176  C
C177  C
C178  C
C179  C
C180  C
C197  CP
C198  CP
C199  C
CN101  B6B-XH-A
CN102  C9E
CN103  B8B-XH-A
CN104  C5G
CN111  C2A
CN112  C2A
CN113  C2A
CN114  C2A
CN115  C2A
CN116  HM-TP08
CN117  HM-TP08
CN118  C2A
CN119  C2A
CN124  HM-TP08
CN125  HM-TP08
CN126  HM-TP08
CN127  HM-TP08
CN128  HM-TP08
IC111  NA  (sections A,B)
PC103  TLX9906
PC104  TLX9906
Q111  MFNG
Q112  MFNG
R147  R
R148  R
R149  R
R150  R
R151  R
R152  R
R153  R
R155  R
R156  R
R157  R
R158  R
R159  R
R168  R
R169  R
R172  R
R173  R
U?#9  WAKU_DEF_A3
sheet 8
C181  C
C182  C
C183  C
C184  C
C441  C
CN120  HM-TP08
CN121  HM-TP08
CN122  HM-TP08
CN123  HM-TP08
D111  D
D112  D
D113  D
D117  D
D118  D
D119  -
D120  D
D121  -
IC112  TLP5231
PC105  TLX9291A
PC106  TLX9291A
PC107  TLX9000
Q113  SSM3K318R
Q114  SSM3K318R
Q115  SSM3K318R
Q116  SSM3K318R
Q119  RN1907_Q1_1  (sections A,B)
Q120  TRN
R160  R
R163  R
R181  R
R182  R
R184  R
R185  R
R186  R
R187  R
R188  R
R189  R
R190  R
R191  R
R192  R
R193  R
TN23  BOX_2
TN24  BOX_2
U?#8  WAKU_DEF_A3

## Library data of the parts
C1-C4 C85-C88 = C: COMPONENTKIND: 0; COMPONENTTYPE: 4; SIZECODESMD: 3216; VAL1: 0.47u(K); VAL2: 100V
C5-C12 C35 C36 C81 C89-C96 C135 C136 C181 = C: COMPONENTKIND: 0; COMPONENTTYPE: 4; SIZECODESMD: 5750; VAL1: 10u(K); VAL2: 50V
C13 C113 C436 C437 = C: COMPONENTKIND: 0; COMPONENTTYPE: 4; SIZECODESMD: 3216; VAL1: 0.1u(K); VAL2: 100V
C14 C114 = C: COMPONENTKIND: 0; COMPONENTTYPE: 4; SIZECODESMD: 2012; VAL1: 33n(J); VAL2: 50V
C15 C115 = C: COMPONENTKIND: 0; COMPONENTTYPE: 4; SIZECODESMD: 1608; VAL1: 1000p(K); VAL2: 50V
C16 C17 C116 C117 = CP: COMP: C; COMPONENTTYPE: 4; VAL1: 150u(M); VAL2: 80V
C444 C445 = C: COMPONENTKIND: 0; COMPONENTTYPE: 4; SIZECODESMD: 1608; VAL1: 47n(K); VAL2: 100V
D1 = DEL_12: COMP: SMBJ78CA; COMPONENTTYPE: 4; VAL3: SMBJ78CA
D322 D323 = D: COMPONENTTYPE: 4; USERCOMPTEXT3: TOSHIBA; VAL3: 1SS403E
IC1 IC101 = IS18: COMP: LTC4364HMS-2#PBF; COMPONENTTYPE: 4; SAVECOUNT: 3; VAL3: LTC4364HMS-2#PBF
L1 L101 = L: COMP: XAL1580-401MED; COMPONENTTYPE: 4; SAVECOUNT: 0; VAL1: 0.4u(M); VAL2: 47A; VAL3: XAL1580-401MED
PC1 PC3 PC4 PC101 PC103 PC104 = TLX9906: COMPONENTTYPE: 4; USERCOMPTEXT3: TOSHIBA
PC2 PC7 PC102 PC107 = TLX9000: COMPONENTTYPE: 4; USERCOMPTEXT3: TOSHIBA
Q1 Q2 Q4-Q9 Q101 Q102 Q104-Q109 = MFNAJ_1: COMP: XPW4R10ANB; COMPONENTTYPE: 4; USERCOMPTEXT3: TOSHIBA; VAL3: XPW4R10ANB
Q11 Q12 Q17 Q111 Q112 Q117 = MFNG: COMP: SSM3K361TU; COMPONENTTYPE: 4; USERCOMPTEXT3: TOSHIBA; VAL3: SSM3K361TU
Q18 Q118 = RN1907_Q1_1: COMP: RN1907; COMPONENTNAME: RN1907_1; COMPONENTTYPE: 8; CaptureCellPackProp: RN1907_Q1_1B; FUNCN: RN1907_2; USERCOMPTEXT3: TOSHIBA; VAL3: RN1907
R1 R11 R14 R17 R21 R24 R27 = R: COMPONENTKIND: 0; COMPONENTTYPE: 4; SIZECODESMD: 2012; VAL1: 10(J)
R2 = R: COMPONENTKIND: 0; COMPONENTTYPE: 4; SIZECODESMD: 1608; VAL1: 100k(D)
R3 R401 R402 R411 R412 = R: COMPONENTKIND: 0; COMPONENTTYPE: 4; SIZECODESMD: 1608; VAL1: 0
R4 = R: COMPONENTKIND: 0; COMPONENTTYPE: 4; SIZECODESMD: 1608; VAL1: 1.8k(D)
R7 = R: COMPONENTKIND: 0; COMPONENTTYPE: 4; SIZECODESMD: 1608; VAL1: 1M(F)
R8 R108 = R: COMPONENTKIND: 0; COMPONENTTYPE: 4; SIZECODESMD: 10052; VAL1: 1m(F)
R64 R65 = R: COMPONENTKIND: 0; COMPONENTTYPE: 4; SIZECODESMD: 1608; VAL1: 100k(J)
R66 R68 R71 R73 R86 R87 R91 = R: COMPONENTKIND: 0; COMPONENTTYPE: 4; SIZECODESMD: 1608; VAL1: 33k(J)
R67 R69 R72 = R: COMPONENTKIND: 0; COMPONENTTYPE: 4; SIZECODESMD: 1608; VAL1: 360(J)
R70 = R: COMPONENTKIND: 0; COMPONENTTYPE: 4; SIZECODESMD: 1608; VAL1: 1.5k(J)
R434 R435 = R: COMPONENTKIND: 0; COMPONENTTYPE: 4; SIZECODESMD: 2012; VAL1: 100(F); VAL2: 125mW
TN11-TN14 TN21-TN24 = BOX_2: COMP: TN; COMPONENTTYPE: 4
U?#15 = WAKU_DEF_A3: AUTHOR: sptcae09; COMPONENTTYPE: 2; DATE: 2025/02/21; DRAWINGNUMBER: RD210-SCHEMATIC1-01; FUNCTION: 48V Input/Output Circuit(BLOCK 0); REVISION: 01; SAVECOUNT: 19; SHEETNUMBER: 1/16; SHTSAVECOUNT: 105; TIME: 10:17:42; TITLE: Automotive 3kW 48V-12V Bidirectional / DC-DC Converter; UPDATEDATE: 2025.2.21; UPDATETIME: 12:03:43
C18-C28 C118-C128 = CP: COMP: C; COMPONENTTYPE: 4; VAL1: 47uF(M); VAL2: 63V
C29-C34 C59-C64 C129-C134 C159-C164 = C: COMPONENTKIND: 0; COMPONENTTYPE: 4; SIZECODESMD: 5750; VAL1: 4.7u(M); VAL2: 100V
C37 C41 C72 C74 C78 C99 C137 C141 C172 C175 C178 C199 = C: COMPONENTKIND: 0; COMPONENTTYPE: 4; SIZECODESMD: 3225; VAL1: 2.2u(K); VAL2: 50V
C38-C40 C73 C75 C77 C83 C100 C110 C138-C140 C173 C174 C177 C183 = C: COMPONENTKIND: 0; COMPONENTTYPE: 4; SIZECODESMD: 1608; VAL1: 0.1u(K); VAL2: 50V
C42 C43 C49 C50 C142 C143 C149 C150 = C: COMPONENTKIND: 0; COMPONENTTYPE: 4; SIZECODESMD: 1608; VAL1: 4.7n(J); VAL2: 50V
C51-C56 C152-C156 = CP: COMP: C; COMPONENTTYPE: 4; VAL1: 39u(M); VAL2: 63V
C57 C58 = CP: COMP: C; COMPONENTTYPE: 4; VAL1: 150u(M); VAL2: 63V
C401 C403 C411 C413 = C: COMPONENTKIND: 0; COMPONENTTYPE: 4; SIZECODESMD: 3216; VAL1: 0.033u(J); VAL2: 50V
C405 C415 = C: COMPONENTKIND: 0; COMPONENTTYPE: 4; SIZECODESMD: 3216; VAL1: 0.1u(K); VAL2: 50V
CN5 CN105 = C2A: COMP: B2B-EH; COMPONENTTYPE: 4; VAL3: B2B-EH
CN8-CN10 CN108-CN110 = B2P-VH: COMPONENTTYPE: 4
CN16 CN17 CN20 CN23 CN29-CN32 CN34 CN116 CN117 CN120 CN123 CN129-CN132 CN134 = HM-TP08: COMP: TSW-101-07-G-S; COMPONENTTYPE: 4; VAL3: TSW-101-07-G-S
CN33 CN133 = HM-TP08: COMP: TSW-101-07-G-S; COMPONENTTYPE: 4; NOTMOUNT: NOT MOUNT; VAL3: TSW-101-07-G-S
D2-D4 D6-D8 D102-D104 D106-D108 = SBD: COMP: CMS10130A; COMPONENTTYPE: 4; USERCOMPTEXT3: TOSHIBA; VAL3: CMS10I30A
D5 D105 = D#1: COMP: NRVUA120VT3G; COMPONENTTYPE: 4; CaptureCellPackProp: D##1; VAL3: NRVUA120VT3G
IC2 IC102 = UCC27211A_00: COMP: UCC27211A-Q1; COMPONENTTYPE: 4; VAL3: UCC27211A-Q1
IC13 IC113 = TC7PZ17FU: COMPONENTTYPE: 4; SAVECOUNT: 3; USERCOMPTEXT3: TOSHIBA
IC14 IC114 = ISO6720_IC13: COMP: ISO6720; COMPONENTTYPE: 4; VAL3: ISO6720
L2 L102 = L: COMP: IHXL-1500VZ-5A; COMPONENTKIND: 116; COMPONENTTYPE: 4; DATE: 2024/5/22; SAVEAREA0: -14227,-538,38802,29317; SAVECOUNT: 24; VAL1: 2.2uH; VAL2: 115A; VAL3: IHXL-1500VZ-5A
R9 R60 = R: COMPONENTKIND: 0; COMPONENTTYPE: 4; SIZECODESMD: 2012; VAL1: 2.2(J)
R10 R13 R16 R20 R23 R26 = R: COMPONENTKIND: 0; COMPONENTTYPE: 4; SIZECODESMD: 2012; VAL1: 1(J)
R12 R15 R18 R22 R25 R28 = R: COMPONENTKIND: 0; COMPONENTTYPE: 4; SIZECODESMD: 1608; VAL1: 10k(J)
R29 R38 = R: COMPONENTKIND: 0; COMPONENTTYPE: 4; SIZECODESMD: 10052; VAL1: 0.5m(F)
R403 R413 = R: COMPONENTKIND: 0; COMPONENTTYPE: 4; SIZECODESMD: 1608; VAL1: 68k(F)
R5111 R5211 = THA: COMP: TH; COMPONENTTYPE: 4; VAL3: TD11-3H103FT
TP4 TP6 TP7 TP9 TP14 TP16 TP17 TP19 TP24 TP26 TP27 TP29 TP104 TP106 TP107 TP109 TP114 TP116 TP117 TP119 TP124 TP126 TP127 TP129 = TP: COMPONENTTYPE: 4
U?#14 = WAKU_DEF_A3: AUTHOR: sptcae09; COMPONENTTYPE: 2; DATE: 2025/02/21; DRAWINGNUMBER: RD210-SCHEMATIC1-01; FUNCTION: Bidirectional DC-DC Converter (BLOCK 0); REVISION: 01; SAVECOUNT: 19; SHEETNUMBER: 2/16; SHTSAVECOUNT: 114; TIME: 17:32:51; TITLE: Automotive 3kW 48V-12V Bidirectional / DC-DC Converter; UPDATEDATE: 2025.2.21; UPDATETIME: 11:55:46
C70 C71 C97 C98 C170 C171 C197 C198 = CP: COMP: C; COMPONENTTYPE: 4; VAL1: 220u(M); VAL2: 10V
C76 C79 C80 C101 C111 C176 C179 C180 = C: COMPONENTKIND: 0; COMPONENTTYPE: 4; SIZECODESMD: 1608; VAL1: 470p(J); VAL2: 50V
CN1 CN101 = B6B-XH-A: COMPONENTTYPE: 4; SAVECOUNT: 10
CN2 CN102 = C9E: COMP: B9B-XH-A; COMPONENTTYPE: 4; VAL3: B9B|XH-A
CN3 CN103 = B8B-XH-A: COMPONENTTYPE: 4
CN4 CN104 = C5G: COMP: B5B-XH-A; COMPONENTTYPE: 4; VAL3: B5B-XH-A
CN6 = C2A: COMP: TSM-102-01-L-SV; COMPONENTTYPE: 4; VAL3: B2B-HX-A
CN7 = C3A: COMP: B3B-XH-A; COMPONENTTYPE: 4; VAL3: B3B-XH-A
CN11-CN15 CN18 CN19 CN111-CN115 CN118 CN119 = C2A: COMP: TSM-102-01-L-SV; COMPONENTTYPE: 4; VAL3: TSM-102-01-L-SV
CN21 CN22 CN24-CN28 CN121 CN122 CN124-CN128 = HM-TP08: COMP: HW-1-S; COMPONENTTYPE: 4; VAL3: HW-1-S
IC11 = TLC2272A-Q1_1: COMP: TLC2272A; COMPONENTNAME: T1C2272A_1; COMPONENTTYPE: 8; CaptureCellPackProp: TLC2272A-Q1_1A; FUNCN: TLC2272A_1; SAVECOUNT: 8; VAL3: TLC2272A-Q1
R47 R55 = R: COMPONENTKIND: 0; COMPONENTTYPE: 4; SIZECODESMD: 1608; VAL1: 10(D)
R48 R49 R51 R52 = R: COMPONENTKIND: 0; COMPONENTTYPE: 4; SIZECODESMD: 1608; VAL1: 20k(D)
R50 R53 R57 R59 = R: COMPONENTKIND: 0; COMPONENTTYPE: 4; SIZECODESMD: 1608; VAL1: 1k(D)
R56 R58 = R: COMPONENTKIND: 0; COMPONENTTYPE: 4; SIZECODESMD: 1608; VAL1: 11k(D)
U?#13 = WAKU_DEF_A3: AUTHOR: sptcae09; COMPONENTTYPE: 2; DATE: 2025/02/21; DRAWINGNUMBER: RD210-SCHEMATIC1-01; FUNCTION: Connector and Isolator (Block 0); REVISION: 01; SAVECOUNT: 19; SHEETNUMBER: 3/16; SHTSAVECOUNT: 99; TIME: 10:18:21; TITLE: Automotive 3kW 48V-12V Bidirectional / DC-DC Converter; UPDATEDATE: 2025.2.21; UPDATETIME: 12:17:46
C82 C84 C182 C184 = C: COMPONENTKIND: 0; COMPONENTTYPE: 4; SIZECODESMD: 1608; VAL1: 10n(J); VAL2: 50V
C440 C441 = C: COMPONENTKIND: 0; COMPONENTTYPE: 4; SIZECODESMD: 1608; VAL1: 22n(K); VAL2: 50V
D11-D13 D17 D18 D20 D111-D113 D117 D118 D120 = D#1: COMPONENTTYPE: 4; CaptureCellPackProp: D##1; USERCOMPTEXT3: TOSHIBA; VAL3: 1SS403E
D15 D16 = BZX84C10_SOT: COMP: SZ1SMA24AT3G; COMPONENTTYPE: 4; VAL3: EDZVFH15B
D19 D21 D119 D121 = BZX84C10_SOT_2: COMP: EDZVFH15B; COMPONENTTYPE: 4; VAL3: EDZVFH15B
IC12 IC112 = TPD7106F: COMPONENTTYPE: 4; USERCOMPTEXT3: TOSHIBA
PC5 PC6 PC105 PC106 = TLX9291A: COMPONENTTYPE: 4; USERCOMPTEXT3: TOSHIBA
Q13-Q16 Q113-Q116 = XPW4R10ANB_Q1: COMP: XPQR3004PB; COMPONENTTYPE: 4; SAVECOUNT: 7; USERCOMPTEXT3: TOSHIBA; VAL3: XPQR3004PB
Q19 = RN1907_Q1_1: COMP: RN1907; COMPONENTNAME: RN1907_1; COMPONENTTYPE: 8; CaptureCellPackProp: RN1907_Q1_1A; FUNCN: RN1907_1; USERCOMPTEXT3: TOSHIBA; VAL3: RN1907
Q20 Q120 = TRN: COMP: 2SC4117-GR; COMPONENTTYPE: 4; USERCOMPTEXT3: TOSHIBA; VAL3: 2SC4117-GR
R63 = R: COMPONENTKIND: 0; COMPONENTTYPE: 4; SIZECODESMD: 1608; VAL1: 330k(F)
R81 R88 R89 R92 = R: COMPONENTKIND: 0; COMPONENTTYPE: 4; SIZECODESMD: 1608; VAL1: 47k(J)
R82 = R: COMPONENTKIND: 0; COMPONENTTYPE: 4; SIZECODESMD: 2012; VAL1: 9.1k(J)
R84 R85 = R: COMPONENTKIND: 0; COMPONENTTYPE: 4; SIZECODESMD: 1608; VAL1: 2.2k(J)
R90 = R: COMPONENTKIND: 0; COMPONENTTYPE: 4; SIZECODESMD: 1608; VAL1: 3.3k(J)
R93 = R: COMPONENTKIND: 0; COMPONENTTYPE: 4; SIZECODESMD: 1608; VAL1: 330k(J)
U?#12 = WAKU_DEF_A3: AUTHOR: sptcae09; COMPONENTTYPE: 2; DATE: 2025/02/21; DRAWINGNUMBER: RD210-SCHEMATIC1-01; FUNCTION: 12V Input/Output Circuit (BLOCK 0); REVISION: 01; SAVECOUNT: 19; SHEETNUMBER: 4/16; SHTSAVECOUNT: 86; TIME: 10:17:42; TITLE: Automotive 3kW 48V-12V Bidirectional / DC-DC Converter; UPDATEDATE: 2025.2.21; UPDATETIME: 12:17:45
R101 = R: COMPONENTKIND: 0; COMPONENTTYPE: 4; FUNCN: R1; SIZECODESMD: 2012; VAL1: 10(J)
R102 = R: COMPONENTKIND: 0; COMPONENTTYPE: 4; FUNCN: R2; SIZECODESMD: 1608; VAL1: 100k(D)
R103 = R: COMPONENTKIND: 0; COMPONENTTYPE: 4; FUNCN: R3; SIZECODESMD: 1608; VAL1: 0
R104 = R: COMPONENTKIND: 0; COMPONENTTYPE: 4; FUNCN: R4; SIZECODESMD: 1608; VAL1: 1.8k(D)
R107 = R: COMPONENTKIND: 0; COMPONENTTYPE: 4; FUNCN: R7; SIZECODESMD: 1608; VAL1: 1M(F)
R164 = R: COMPONENTKIND: 0; COMPONENTTYPE: 4; FUNCN: R64; SIZECODESMD: 1608; VAL1: 100k(J)
R165 = R: COMPONENTKIND: 0; COMPONENTTYPE: 4; FUNCN: R65; SIZECODESMD: 1608; VAL1: 100k(J)
R166 = R: COMPONENTKIND: 0; COMPONENTTYPE: 4; FUNCN: R66; SIZECODESMD: 1608; VAL1: 33k(J)
R167 = R: COMPONENTKIND: 0; COMPONENTTYPE: 4; FUNCN: R67; SIZECODESMD: 1608; VAL1: 360(J)
R170 = R: COMPONENTKIND: 0; COMPONENTTYPE: 4; FUNCN: R70; SIZECODESMD: 1608; VAL1: 1.5k(J)
R171 = R: COMPONENTKIND: 0; COMPONENTTYPE: 4; FUNCN: R71; SIZECODESMD: 1608; VAL1: 33k(J)
U?#11 = WAKU_DEF_A3: AUTHOR: sptcae09; COMPONENTTYPE: 2; DATE: 2025/02/21; DRAWINGNUMBER: RD210-SCHEMATIC1-01; FUNCTION: 48V Input/Output Circuit(BLOCK 1); REVISION: 01; SAVECOUNT: 19; SHEETNUMBER: 5/16; SHTSAVECOUNT: 57; TIME: 10:17:42; TITLE: Automotive 3kW 48V-12V Bidirectional / DC-DC Converter; UPDATEDATE: 2025.2.21; UPDATETIME: 12:17:46
C151 = CP: COMP: C; COMPONENTTYPE: 4; VAL1: 39uF(M); VAL2: 63V
C157 = CP: COMP: C; COMPONENTTYPE: 4; VAL1: 150uF(M); VAL2: 63V
C158 = C_00: COMP: C; COMPONENTTYPE: 4; SAVECOUNT: 2; VAL1: 150u(M); VAL2: 63V
R109 = R: COMPONENTKIND: 0; COMPONENTTYPE: 4; FUNCN: R9; SIZECODESMD: 2012; VAL1: 2.2(J)
R110 = R: COMPONENTKIND: 0; COMPONENTTYPE: 4; FUNCN: R10; SIZECODESMD: 2012; VAL1: 1(J)
R111 = R: COMPONENTKIND: 0; COMPONENTTYPE: 4; FUNCN: R11; SIZECODESMD: 2012; VAL1: 10(J)
R112 = R: COMPONENTKIND: 0; COMPONENTTYPE: 4; FUNCN: R12; SIZECODESMD: 1608; VAL1: 10k(J)
R113 = R: COMPONENTKIND: 0; COMPONENTTYPE: 4; FUNCN: R13; SIZECODESMD: 2012; VAL1: 1(J)
R114 = R: COMPONENTKIND: 0; COMPONENTTYPE: 4; FUNCN: R14; SIZECODESMD: 2012; VAL1: 10(J)
R115 = R: COMPONENTKIND: 0; COMPONENTTYPE: 4; FUNCN: R15; SIZECODESMD: 1608; VAL1: 10k(J)
R116 = R: COMPONENTKIND: 0; COMPONENTTYPE: 4; FUNCN: R16; SIZECODESMD: 2012; VAL1: 1(J)
R117 = R: COMPONENTKIND: 0; COMPONENTTYPE: 4; FUNCN: R17; SIZECODESMD: 2012; VAL1: 10(J)
R118 = R: COMPONENTKIND: 0; COMPONENTTYPE: 4; FUNCN: R18; SIZECODESMD: 1608; VAL1: 10k(J)
R120 = R: COMPONENTKIND: 0; COMPONENTTYPE: 4; FUNCN: R20; SIZECODESMD: 2012; VAL1: 1(J)
R121 = R: COMPONENTKIND: 0; COMPONENTTYPE: 4; FUNCN: R21; SIZECODESMD: 2012; VAL1: 10(J)
R122 = R: COMPONENTKIND: 0; COMPONENTTYPE: 4; FUNCN: R22; SIZECODESMD: 1608; VAL1: 10k(J)
R123 = R: COMPONENTKIND: 0; COMPONENTTYPE: 4; FUNCN: R23; SIZECODESMD: 2012; VAL1: 1(J)
R124 = R: COMPONENTKIND: 0; COMPONENTTYPE: 4; FUNCN: R24; SIZECODESMD: 2012; VAL1: 10(J)
R125 = R: COMPONENTKIND: 0; COMPONENTTYPE: 4; FUNCN: R25; SIZECODESMD: 1608; VAL1: 10k(J)
R126 = R: COMPONENTKIND: 0; COMPONENTTYPE: 4; FUNCN: R26; SIZECODESMD: 2012; VAL1: 1(J)
R127 = R: COMPONENTKIND: 0; COMPONENTTYPE: 4; FUNCN: R27; SIZECODESMD: 2012; VAL1: 10(J)
R128 = R: COMPONENTKIND: 0; COMPONENTTYPE: 4; FUNCN: R28; SIZECODESMD: 1608; VAL1: 10k(J)
R129 = R: COMPONENTKIND: 0; COMPONENTTYPE: 4; FUNCN: R29; SIZECODESMD: 10052; VAL1: 0.5m(F)
R138 = R: COMPONENTKIND: 0; COMPONENTTYPE: 4; FUNCN: R38; SIZECODESMD: 10052; VAL1: 0.5m(F)
U?#10 = WAKU_DEF_A3: AUTHOR: e5025010; COMPONENTTYPE: 2; DATE: 2025/02/21; DRAWINGNUMBER: RD210-SCHEMATIC1-01; FUNCTION: Bidirectional DC-DC Converter (BLOCK 1); REVISION: 01; SAVECOUNT: 19; SHEETNUMBER: 6/16; SHTSAVECOUNT: 78; TIME: 18:54:05; TITLE: Automotive 3kW 48V-12V Bidirectional / DC-DC Converter; UPDATEDATE: 2025.2.21; UPDATETIME: 11:59:42
IC111 = TLC2272A-Q1_1: COMP: TLC2272A; COMPONENTNAME: TLC2272A_2; COMPONENTTYPE: 8; CaptureCellPackProp: TLC2272A-Q1_1B; FUNCN: TLC2272A_2; VAL3: TLC2272A-Q1; SAVECOUNT: 8
R147 = R: COMPONENTKIND: 0; COMPONENTTYPE: 4; FUNCN: R47; SIZECODESMD: 1608; VAL1: 10(D)
R148 = R: COMPONENTKIND: 0; COMPONENTTYPE: 4; FUNCN: R48; SIZECODESMD: 1608; VAL1: 20k(D)
R149 = R: COMPONENTKIND: 0; COMPONENTTYPE: 4; FUNCN: R49; SIZECODESMD: 1608; VAL1: 20k(D)
R150 = R: COMPONENTKIND: 0; COMPONENTTYPE: 4; FUNCN: R50; SIZECODESMD: 1608; VAL1: 1k(D)
R151 = R: COMPONENTKIND: 0; COMPONENTTYPE: 4; FUNCN: R51; SIZECODESMD: 1608; VAL1: 20k(D)
R152 = R: COMPONENTKIND: 0; COMPONENTTYPE: 4; FUNCN: R52; SIZECODESMD: 1608; VAL1: 20k(D)
R153 = R: COMPONENTKIND: 0; COMPONENTTYPE: 4; FUNCN: R53; SIZECODESMD: 1608; VAL1: 1k(D)
R155 = R: COMPONENTKIND: 0; COMPONENTTYPE: 4; FUNCN: R55; SIZECODESMD: 1608; VAL1: 10(D)
R156 = R: COMPONENTKIND: 0; COMPONENTTYPE: 4; FUNCN: R56; SIZECODESMD: 1608; VAL1: 11k(D)
R157 = R: COMPONENTKIND: 0; COMPONENTTYPE: 4; FUNCN: R57; SIZECODESMD: 1608; VAL1: 1k(D)
R158 = R: COMPONENTKIND: 0; COMPONENTTYPE: 4; FUNCN: R58; SIZECODESMD: 1608; VAL1: 11k(D)
R159 = R: COMPONENTKIND: 0; COMPONENTTYPE: 4; FUNCN: R59; SIZECODESMD: 1608; VAL1: 1k(D)
R168 = R: COMPONENTKIND: 0; COMPONENTTYPE: 4; FUNCN: R68; SIZECODESMD: 1608; VAL1: 33k(J)
R169 = R: COMPONENTKIND: 0; COMPONENTTYPE: 4; FUNCN: R69; SIZECODESMD: 1608; VAL1: 360(J)
R172 = R: COMPONENTKIND: 0; COMPONENTTYPE: 4; FUNCN: R72; SIZECODESMD: 1608; VAL1: 360(J)
R173 = R: COMPONENTKIND: 0; COMPONENTTYPE: 4; FUNCN: R73; SIZECODESMD: 1608; VAL1: 33k(J)
U?#9 = WAKU_DEF_A3: AUTHOR: sptcae09; COMPONENTTYPE: 2; DATE: 2025/02/21; DRAWINGNUMBER: RD210-SCHEMATIC1-01; FUNCTION: Connector and Isolator (Block 1); REVISION: 01; SAVECOUNT: 19; SHEETNUMBER: 7/16; SHTSAVECOUNT: 71; TIME: 10:18:21; TITLE: Automotive 3kW 48V-12V Bidirectional / DC-DC Converter; UPDATEDATE: 2025.2.21; UPDATETIME: 12:17:46
Q119 = RN1907_Q1_1: COMP: RN1907; COMPONENTNAME: RN1907_2; COMPONENTTYPE: 8; CaptureCellPackProp: RN1907_Q1_1B; FUNCN: RN1907_2; USERCOMPTEXT3: TOSHIBA; VAL3: RN1907
R160 = R: COMPONENTKIND: 0; COMPONENTTYPE: 4; FUNCN: R60; SIZECODESMD: 2012; VAL1: 2.2(J)
R163 = R: COMPONENTKIND: 0; COMPONENTTYPE: 4; FUNCN: R63; SIZECODESMD: 1608; VAL1: 330k(F)
R181 = R: COMPONENTKIND: 0; COMPONENTTYPE: 4; FUNCN: R81; SIZECODESMD: 1608; VAL1: 47k(J)
R182 = R: COMPONENTKIND: 0; COMPONENTTYPE: 4; FUNCN: R82; SIZECODESMD: 2012; VAL1: 9.1k(J)
R184 = R: COMPONENTKIND: 0; COMPONENTTYPE: 4; FUNCN: R84; SIZECODESMD: 1608; VAL1: 2.2k(J)
R185 = R: COMPONENTKIND: 0; COMPONENTTYPE: 4; FUNCN: R85; SIZECODESMD: 1608; VAL1: 2.2k(J)
R186 = R: COMPONENTKIND: 0; COMPONENTTYPE: 4; FUNCN: R86; SIZECODESMD: 1608; VAL1: 33k(J)
R187 = R: COMPONENTKIND: 0; COMPONENTTYPE: 4; FUNCN: R87; SIZECODESMD: 1608; VAL1: 33k(J)
R188 = R: COMPONENTKIND: 0; COMPONENTTYPE: 4; FUNCN: R88; SIZECODESMD: 1608; VAL1: 47k(J)
R189 = R: COMPONENTKIND: 0; COMPONENTTYPE: 4; FUNCN: R89; SIZECODESMD: 1608; VAL1: 47k(J)
R190 = R: COMPONENTKIND: 0; COMPONENTTYPE: 4; FUNCN: R90; SIZECODESMD: 1608; VAL1: 3.3k(J)
R191 = R: COMPONENTKIND: 0; COMPONENTTYPE: 4; FUNCN: R91; SIZECODESMD: 1608; VAL1: 33k(J)
R192 = R: COMPONENTKIND: 0; COMPONENTTYPE: 4; FUNCN: R92; SIZECODESMD: 1608; VAL1: 47k(J)
R193 = R: COMPONENTKIND: 0; COMPONENTTYPE: 4; FUNCN: R93; SIZECODESMD: 1608; VAL1: 330k(J)
U?#8 = WAKU_DEF_A3: AUTHOR: sptcae09; COMPONENTTYPE: 2; DATE: 2025/02/21; DRAWINGNUMBER: RD210-SCHEMATIC1-01; FUNCTION: 12V Input/Output Circuit (BLOCK 1); REVISION: 01; SAVECOUNT: 19; SHEETNUMBER: 8/16; SHTSAVECOUNT: 62; TIME: 10:17:42; TITLE: Automotive 3kW 48V-12V Bidirectional / DC-DC Converter; UPDATEDATE: 2025.2.21; UPDATETIME: 12:17:46

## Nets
GND-1: C72.2 C73.2 C74.2 C75.2 C77.1 C78.1 C100.1 CN1.3 CN2.9 CN3.3 CN4.4 IC11.4 IC14.4 PC2.3 PC7.3 Q18.1 Q18.4 Q19.1 Q19.4
GND-2: C110.1 C172.2 C173.2 C174.2 C175.2 C177.1 C178.1 CN101.3 CN102.9 CN103.3 CN104.4 IC111.4 IC114.4 PC102.3 PC107.3 Q118.1 Q118.4 Q119.1 Q119.4
GND_5V_I0_0: C98.2(1) CN27.1
GND_5V_I0_1: C70.2(1) CN25.1
GND_5V_I0_2: C97.2(1) CN26.1
GND_5V_I1_0: C198.2(1) CN127.1
GND_5V_I1_1: C170.2(1) CN125.1
GND_5V_I1_2: C197.2(1) CN126.1
GND_12R0_SYS_I0_0: C99.2 CN28.1
GND_12R0_SYS_I0_1: C71.2(1) CN24.1
GND_12R0_SYS_I1_0: C199.2 CN128.1
GND_12R0_SYS_I1_1: C171.2(1) CN124.1
GND_P-1: C2.1 C4.1 C6.1 C8.1 C10.1 C12.1 C13.1 C14.2 C15.1 C16.2(1) C17.2(1) C18.2(1) C19.2(1) C20.2(1) C21.2(1) C22.2(1) C23.2(1) C24.2(1) C25.2(1) C26.2(1) C27.2(1) C28.2(1) C29.1 C30.1 C31.1 C32.1 C33.1 C34.1 C35.1 C36.1 C37.2 C38.2 C39.1 C40.1 C42.2 C43.2 C49.2 C50.2 C51.2(1) C52.2(1) C53.2(1) C54.2(1) C55.2(1) C56.2(1) C57.2(1) C58.2(1) C59.1 C60.1 C61.1 C62.1 C63.1 C64.1 C79.1 C81.1 C83.2 C86.1 C88.1 C90.1 C92.1 C94.1 C96.1 C101.1 C440.2 C444.2 CN1.6 CN3.1 CN7.3 CN16.1 CN17.1 CN20.1 CN34.1 D1.1 D16.1 D17.1(A) IC1.12 IC1.16 IC2.7(VSS) IC2.9(GND) IC12.2(TEST) IC12.7(IN2) IC12.8(GND1) IC12.9(GND2) IC13.2 IC14.5 Q7.S Q8.S Q9.S R4.1 R22.2 R25.2 R28.2 R50.2 R51.1 R57.2 R58.1 R65.1 R88.1 R89.1 R93.1 TN12.1(spin.1) TN12.2(spin.2) TN14.1(spin.1) TN14.2(spin.2) TP17.1 TP19.1
GND_P-2: C111.1 C113.1 C114.2 C115.1 C116.2(1) C117.2(1) C118.2(1) C119.2(1) C120.2(1) C121.2(1) C122.2(1) C123.2(1) C124.2(1) C125.2(1) C126.2(1) C127.2(1) C128.2(1) C129.1 C130.1 C131.1 C132.1 C133.1 C134.1 C135.1 C136.1 C137.2 C138.2 C139.1 C140.1 C142.2 C143.2 C149.2 C150.2 C151.2(1) C152.2(1) C153.2(1) C154.2(1) C155.2(1) C156.2(1) C157.2(1) C158.2 C159.1 C160.1 C161.1 C162.1 C163.1 C164.1 C179.1 C181.1 C183.2 C441.2 C445.2 CN101.6 CN103.1 CN116.1 CN117.1 CN120.1 CN134.1 D117.1(A) IC101.12 IC101.16 IC102.7(VSS) IC102.9(GND) IC112.2(TEST) IC112.7(IN2) IC112.8(GND1) IC112.9(GND2) IC113.2 IC114.5 Q107.S Q108.S Q109.S R104.1 R122.2 R125.2 R128.2 R150.2 R151.1 R157.2 R158.1 R165.1 R188.1 R189.1 R193.1 TN22.1(spin.1) TN22.2(spin.2) TN24.1(spin.1) TN24.2(spin.2) TP117.1 TP119.1
VDDA-1: C77.2 C78.2 CN4.5 IC11.8
VDDA-2: C177.2 C178.2 CN104.5 IC111.8
VDDIO-1: C72.1 C73.1 C100.2 CN1.1 IC14.1
VDDIO-2: C110.2 C172.1 C173.1 CN101.1 IC114.1
DIAG_0-1: CN3.6 PC7.4
DIAG_0-2: CN103.6 PC107.4
H_EN_0-1: CN4.3 Q18.2
H_EN_0-2: CN104.3 Q118.2
L_IN1_0-1: CN3.4 Q19.2
L_IN1_0-2: CN103.4 Q119.2
MES_EN_0-1: CN2.8 Q18.5
MES_EN_0-2: CN102.8 Q118.5
PowerGood_0-1: CN4.1 PC2.4
PowerGood_0-2: CN104.1 PC102.4
PWM_H_0-1: CN2.2 IC14.2
PWM_H_0-2: CN102.2 IC114.2
PWM_L_0-1: CN2.1 IC14.3
PWM_L_0-2: CN102.1 IC114.3
Q18-C-3pin: Q18.3 R69.1 R72.1
Q118-C-3pin: Q118.3 R169.1 R172.1
SIG0011: IC1.13 R70.1
SIG0012: IC1.9 IC1.10 PC1.4(3) Q17.2(S) R65.2
SIG0013: Q17.3(D) R64.1
SIG0015: C14.1 IC1.15
SIG0017: C13.2 IC1.8 R1.1 R64.2
SIG0019: C5.1 C6.2
SIG00110: C9.1 C10.2
SIG00113: C7.1 C8.2
SIG00115: C16.1(2) C17.1(2) IC1.1 L1.1 R8.2
SIG00116: C1.1 C2.2
SIG00117: C3.1 C4.2
SIG00118: C11.1 C12.2
SIG00121: PC2.2 R70.2 R71.1
SIG00124: R3.1 R4.2
SIG00125: PC1.6(4) Q17.1(G)
SIG00127: PC1.3(2) R66.1 R67.1
SIG00129: Q18.6 R67.2
SIG00135: D322.2(A) IC1.6 Q1.G Q2.G R7.1 R434.1
SIG00136: IC1.2 IC1.5 Q1.S Q2.S R7.2 R8.1
SIG00138: C15.2 IC1.11 R2.1 R3.2
SIG00139: C444.1 D322.1(C) R434.2
SIG00458: D17.2(C) R81.2 R92.1
SIG00459: D19.2(1) D21.2(1)
SIG00461: C82.1 IC12.3(CP1)
SIG00462: IC12.5(STBY) PC5.3 R89.2
SIG00463: PC5.2 R84.2 R86.1
SIG00464: PC6.2 R85.2 R87.1
SIG00465: C82.2 IC12.1(CP1-)
SIG00466: IC12.6(IN1) PC6.3 R88.2
SIG00467: Q19.3 R84.1
SIG00469: CN23.1 D11.2(C) D12.2(C) D13.2(C) R60.1
SIG00470: C81.2 IC12.4(VDD) R60.2
SIG00472: IC12.10(DIAG) R90.1
SIG00473: C83.1 IC12.13(CPV)
SIG00474: C84.2 IC12.16(CP2-)
SIG00475: C84.1 IC12.14(CP2)
SIG00476: IC12.12(OUT1) R81.1 R82.1
SIG00477: D20.2(C) R82.2
SIG00479: PC7.2 R90.2 R91.1
SIG00481: C85.1 C86.2
SIG00482: C91.1 C92.2
SIG00483: C89.1 C90.2
SIG00484: C95.1 C96.2
SIG00485: C93.1 C94.2
SIG00486: D15.2 D16.2
SIG00487: C87.1 C88.2
SIG00489: D18.2(C) Q20.1(B) R93.2
SIG00490: C440.1 CN21.1 D19.1(2) D20.1(A) Q13.1(G) Q14.1(G) Q15.1(G) Q16.1(G) Q20.3(C) R63.2 R92.2
SIG00491: CN22.1 D18.1(A) D21.1(2) Q13.2(S) Q14.2(S) Q15.2(S) Q16.2(S) Q20.2(E) R63.1
SIG00492: Q19.6 R85.1
SIG00533: Q117.3(D) R164.1
SIG00534: R103.1 R104.2
SIG00535: C116.1(2) C117.1(2) IC101.1 L101.1 R108.2
SIG00536: IC101.9 IC101.10 PC101.4(3) Q117.2(S) R165.2
SIG00538: PC101.6(4) Q117.1(G)
SIG00539: D323.2(A) IC101.6 Q101.G Q102.G R107.1 R435.1
SIG00540: PC102.2 R170.2 R171.1
SIG00541: C115.2 IC101.11 R102.1 R103.2
SIG00542: C113.2 IC101.8 R101.1 R164.2
SIG00543: IC101.13 R170.1
SIG00544: C114.1 IC101.15
SIG00545: IC101.2 IC101.5 Q101.S Q102.S R107.2 R108.1
SIG00546: PC101.3(2) R166.1 R167.1
SIG00548: Q118.6 R167.2
SIG00549: C445.1 D323.1(C) R435.2
SIG00663: Q106.G R116.2 R117.2 R118.1 TP126.1
SIG00664: CN129.1 Q105.G R113.2 R114.2 R115.1
SIG00665: Q109.G R126.2 R127.2 R128.1 TP129.1
SIG00666: IC113.1 IC114.7
SIG00667: C141.1 C437.1 D105.2(C) IC102.2(HB)
SIG00668: Q104.G R110.2 R111.2 R112.1 TP124.1
SIG00669: C142.1 CN130.1 Q104.D Q105.D Q106.D R129.2 R411.1 TP104.1 TP106.1
SIG00670: CN132.1 Q108.G R123.2 R124.2 R125.1
SIG00671: C141.2 C437.2 CN131.1 CN133.1 IC102.4(HS) L102.1 Q104.S Q105.S Q106.S Q107.D Q108.D Q109.D R112.2 R115.2 R118.2 R413.1 TP107.1 TP109.1 TP114.1 TP116.1
SIG00672: Q107.G R120.2 R121.2 R122.1 TP127.1
SIG00673: D106.1(A) R120.1
SIG00674: D105.1(A) R109.2
SIG00675: IC102.5(HI) IC113.6
SIG00676: D107.1(A) R123.1
SIG00677: D104.1(A) R116.1
SIG00678: D102.1(A) R110.1
SIG00680: D106.2(C) D107.2(C) D108.2(C) IC102.8(LO) R121.1 R124.1 R127.1
SIG00681: C149.1 C415.2 CN110.1 L102.2 R138.1 R412.1
SIG00682: C413.1 CN109.2 R412.2
SIG00684: D103.1(A) R113.1
SIG00685: IC102.6(LI) IC113.4
SIG00686: IC113.3 IC114.6
SIG00687: D108.1(A) R126.1
SIG00688: C415.1 CN110.2 R413.2
SIG00690: D102.2(C) D103.2(C) D104.2(C) IC102.3(HO) R111.1 R114.1 R117.1
SIG00691: C411.2 CN108.2 R411.2
SIG00692: CN105.2 R5211.1
SIG00693: CN105.1 R5211.2
SIG00744: C180.1 IC111.6 R158.2 R159.1
SIG00745: PC104.3(2) R172.2 R173.1
SIG00747: PC103.3(2) R168.1 R169.2
SIG00748: C176.1 IC111.2(3) R152.2 R153.1
SIG00749: R148.2 R149.1
SIG00750: R151.2 R152.1
SIG00751: C179.2 IC111.5 PC104.4(3) Q112.2(S) R157.1
SIG00752: C171.1(2) CN103.7 CN115.1
SIG00753: CN119.2 R147.1 R148.1
SIG00755: C197.1(2) CN104.2 CN113.1
SIG00756: C111.2 IC111.3(2) PC103.4(3) Q111.2(S) R150.1
SIG00757: C170.1(2) CN103.2 CN114.1
SIG00758: CN118.2 R155.1 R156.1
SIG00759: PC104.6(4) Q112.1(G)
SIG00760: PC103.6(4) Q111.1(G)
SIG00761: Q112.3(D) R156.2
SIG00762: Q111.3(D) R149.2
SIG00763: C199.1 CN101.5 CN112.1
SIG00764: C198.1(2) CN101.4 CN111.1
SIG00847: IC112.10(DIAG) R190.1
SIG00848: C184.2 IC112.16(CP2-)
SIG00849: C441.1 CN121.1 D119.1(2) D120.1(A) Q113.1(G) Q114.1(G) Q115.1(G) Q116.1(G) Q120.3(C) R163.2 R192.2
SIG00850: PC107.2 R190.2 R191.1
SIG00851: IC112.6(IN1) PC106.3 R188.2
SIG00852: D120.2(C) R182.2
SIG00853: D118.2(C) Q120.1(B) R193.2
SIG00854: Q119.6 R185.1
SIG00855: CN123.1 D111.2(C) D112.2(C) D113.2(C) R160.1
SIG00856: PC105.2 R184.2 R186.1
SIG00857: IC112.5(STBY) PC105.3 R189.2
SIG00858: Q119.3 R184.1
SIG00859: D119.2(1) D121.2(1)
SIG00860: CN122.1 D118.1(A) D121.1(2) Q113.2(S) Q114.2(S) Q115.2(S) Q116.2(S) Q120.2(E) R163.1
SIG00861: C181.2 IC112.4(VDD) R160.2
SIG00862: PC106.2 R185.2 R187.1
SIG00863: C183.1 IC112.13(CPV)
SIG00864: C182.2 IC112.1(CP1-)
SIG00865: IC112.12(OUT1) R181.1 R182.1
SIG00866: C182.1 IC112.3(CP1)
SIG00867: C184.1 IC112.14(CP2)
SIG00868: D117.2(C) R181.2 R192.1
SIG002147: C405.1 CN10.2 R403.2
SIG002148: C403.1 CN9.2 R402.2
SIG002149: C49.1 C405.2 CN10.1 L2.2 R38.1 R402.1
SIG002150: D8.1(A) R26.1
SIG002152: D7.1(A) R23.1
SIG002153: CN32.1 Q8.G R23.2 R24.2 R25.1
SIG002154: D6.1(A) R20.1
SIG002156: Q7.G R20.2 R21.2 R22.1 TP27.1
SIG002157: Q6.G R16.2 R17.2 R18.1 TP26.1
SIG002159: D4.1(A) R16.1
SIG002160: CN29.1 Q5.G R13.2 R14.2 R15.1
SIG002162: D3.1(A) R13.1
SIG002164: D2.1(A) R10.1
SIG002165: Q4.G R10.2 R11.2 R12.1 TP24.1
SIG002166: D5.1(A) R9.2
SIG002167: IC2.5(HI) IC13.6
SIG002168: IC13.1 IC14.7
SIG002169: IC13.3 IC14.6
SIG002171: IC2.6(LI) IC13.4
SIG002174: C41.1 C436.1 D5.2(C) IC2.2(HB)
SIG002176: Q9.G R26.2 R27.2 R28.1 TP29.1
SIG002177: D2.2(C) D3.2(C) D4.2(C) IC2.3(HO) R11.1 R14.1 R17.1
SIG002178: CN5.1 R5111.2
SIG002179: CN5.2 R5111.1
SIG002180: D6.2(C) D7.2(C) D8.2(C) IC2.8(LO) R21.1 R24.1 R27.1
SIG002182: C41.2 C436.2 CN31.1 CN33.1 IC2.4(HS) L2.1 Q4.S Q5.S Q6.S Q7.D Q8.D Q9.D R12.2 R15.2 R18.2 R403.1 TP7.1 TP9.1 TP14.1 TP16.1
SIG002186: C42.1 CN30.1 Q4.D Q5.D Q6.D R29.2 R401.1 TP4.1 TP6.1
SIG002187: C401.2 CN8.2 R401.2
SIG003131: PC3.3(2) R68.1 R69.2
SIG003133: PC3.6(4) Q11.1(G)
SIG003135: R48.2 R49.1
SIG003136: R51.2 R52.1
SIG003137: C101.2 IC11.3(2) PC3.4(3) Q11.2(S) R50.1
SIG003139: C76.1 IC11.2(3) R52.2 R53.1
SIG003140: PC4.3(2) R72.2 R73.1
SIG003142: C79.2 IC11.5 PC4.4(3) Q12.2(S) R57.1
SIG003148: C80.1 IC11.6 R58.2 R59.1
SIG003150: CN19.2 R47.1 R48.1
SIG003152: CN18.2 R55.1 R56.1
SIG003153: C99.1 CN1.5 CN12.1
SIG003154: C70.1(2) CN3.2 CN14.1
SIG003155: C71.1(2) CN3.7 CN15.1
SIG003156: C97.1(2) CN4.2 CN13.1
SIG003157: C98.1(2) CN1.4 CN11.1
SIG003158: Q11.3(D) R49.2
SIG003159: Q12.3(D) R56.2
SIG003160: PC4.6(4) Q12.1(G)
STBY_0-1: CN3.5 Q19.5
STBY_0-2: CN103.5 Q119.5
V_B0-1: C76.2 CN2.7 IC11.1 R53.2
V_B0-2: C176.2 CN102.7 IC111.1 R153.2
V_C0-1: C80.2 CN2.6 IC11.7 R59.2
V_C0-2: C180.2 CN102.6 IC111.7 R159.2
VP_5R0-1: C74.1 C75.1 CN1.2 PC1.1 PC3.1 PC4.1 PC5.1 PC6.1 R66.2 R68.2 R73.2 R86.2 R87.2
VP_5R0-2: C174.1 C175.1 CN101.2 PC101.1 PC103.1 PC104.1 PC105.1 PC106.1 R166.2 R168.2 R173.2 R186.2 R187.2
VP_5V_I0_0: C39.2 C40.2 CN11.2 IC13.5 IC14.8
VP_5V_I0_1: CN14.2 PC5.4 PC6.4 PC7.1 R91.2
VP_5V_I0_2: CN13.2 PC2.1 R71.2
VP_5V_I1_0: C139.2 C140.2 CN111.2 IC113.5 IC114.8
VP_5V_I1_1: CN114.2 PC105.4 PC106.4 PC107.1 R191.2
VP_5V_I1_2: CN113.2 PC102.1 R171.2
VP_12R0_SYS_I0_0: C35.2 C36.2 C37.1 C38.1 CN12.2 IC2.1(VDD) R9.1
VP_12R0_SYS_I0_1: CN15.2 D11.1(A)
VP_12R0_SYS_I1_0: C135.2 C136.2 C137.1 C138.1 CN112.2 IC102.1(VDD) R109.1
VP_12R0_SYS_I1_1: CN115.2 D111.1(A)
VP_H: C1.2 C3.2 C5.2 C7.2 C9.2 C11.2 CN6.1 CN6.2 D1.2 Q1.D Q2.D Q101.D Q102.D R1.2 R2.2 R101.2 R102.2 TN11.1(spin.1) TN11.2(spin.2) TN21.1(spin.1) TN21.2(spin.2) ; also on sheet 4 8
VP_H_0-1: C18.1(2) C19.1(2) C20.1(2) C21.1(2) C22.1(2) C23.1(2) C24.1(2) C25.1(2) C26.1(2) C27.1(2) C28.1(2) C29.2 C30.2 C31.2 C32.2 C33.2 C34.2 C43.1 C401.1 CN8.1 CN19.1 L1.2 R29.1 R47.2
VP_H_0-2: C118.1(2) C119.1(2) C120.1(2) C121.1(2) C122.1(2) C123.1(2) C124.1(2) C125.1(2) C126.1(2) C127.1(2) C128.1(2) C129.2 C130.2 C131.2 C132.2 C133.2 C134.2 C143.1 C411.1 CN108.1 CN119.1 L101.2 R129.1 R147.2
VP_L: C85.2 C87.2 C89.2 C91.2 C93.2 C95.2 CN7.1 D13.1(A) D15.1 D113.1(A) Q15.3(D) Q16.3(D) Q115.3(D) Q116.3(D) TN13.1(spin.1) TN13.2(spin.2) TN23.1(spin.1) TN23.2(spin.2) ; also on sheet 1 5
VP_L_0-1: C50.1 C51.1(2) C52.1(2) C53.1(2) C54.1(2) C55.1(2) C56.1(2) C57.1(2) C58.1(2) C59.2 C60.2 C61.2 C62.2 C63.2 C64.2 C403.2 CN3.8 CN9.1 CN18.1 D12.1(A) Q13.3(D) Q14.3(D) R38.2 R55.2
VP_L_0-2: C150.1 C151.1(2) C152.1(2) C153.1(2) C154.1(2) C155.1(2) C156.1(2) C157.1(2) C158.1 C159.2 C160.2 C161.2 C162.2 C163.2 C164.2 C413.2 CN103.8 CN109.1 CN118.1 D112.1(A) Q113.3(D) Q114.3(D) R138.2 R155.2

Not connected (* = marked no-connect by the designer): CN2 3 4 5; CN7 2; CN102 3 4 5; IC1 3 4 7 14; IC12 11(OUT2) 15(N.C.); IC101 3 4 7 14; IC112 11(OUT2) 15(N.C.)

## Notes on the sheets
sheet 9
- 2/2
- 1/2
sheet 10
- ¦GND_12R0_SYS_I1_0 is connected to GND_P-2
- ¦GND_5V_I1_0 is connected to GND_P-2
- ¦CN101 is connected to CN101 of RD210-SCHEMATIC2
- ¦
- ¦
- ¦CN102 is connected to CN102 of RD210-SCHEMATIC2
- 1/2
- ¦GND_12R0_SYS_I1_1 is connected to GND_P-2
- ¦GND_5V_I1_1 is connected to GND_P-2
- ¦CN103 is connected to CN103 of RD210-SCHEMATIC2
- ¦
- ¦
- 2/2
- ¦GND_5V_I1_2 is connected to GND_P-2
- ¦CN104 is connected to CN104 of RD210-SCHEMATIC2
- ¦
sheet 11
- ¦CN108 is connected to CN618 of RD210-SCHEMATIC2
- X6
- X11
- ¦CN110 is connected to CN920 of RD210-SCHEMATIC2
- ¦CN109 is connected to CN208 of RD210-SCHEMATIC2
- ¦CN105 is connected to CN105 of RD210-SCHEMATIC2
- X6
- X6
- X2
sheet 12
- 1/2
- 2/2
sheet 13
- 2/2
- 1/2
sheet 14
- ¦GND_12R0_SYS_I0_0 is connected to GND_P-1
- ¦GND_5V_I0_0 is connected to GND_P-1
- ¦CN1 is connected to CN1 of RD210-SCHEMATIC2
- ¦
- ¦
- ¦CN2 is connected to CN2 of RD210-SCHEMATIC2
- ¦CN6 is connected to CN6 of RD210-SCHEMATIC2
- 1/2
- ¦CN7 is connected to CN7 of RD210-SCHEMATIC2
- ¦GND_12R0_SYS_I0_1 is connected to GND_P-1
- ¦GND_5V_I0_1 is connected to GND_P-1
- ¦CN3 is connected to CN3 of RD210-SCHEMATIC2
- ¦
- ¦
- 2/2
- ¦GND_5V_I0_2 is connected to GND_P-1
- ¦CN4 is connected to CN4 of RD210-SCHEMATIC2
- ¦
sheet 15
- ¦CN8 is connected to CN508 of RD210-SCHEMATIC2
- X6
- X11
- ¦CN10 is connected to CN910 of RD210-SCHEMATIC2
- ¦CN9 is connected to CN509 of RD210-SCHEMATIC2
- ¦CN5 is connected to CN5 of RD210-SCHEMATIC2
- X6
- X6
- X2
sheet 16
- 1/2
- 2/2
